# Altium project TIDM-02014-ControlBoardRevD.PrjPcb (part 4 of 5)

## Sheet Safety MCU.SchDoc
size 431 x 279 mm; Date: Not shown in title block; ApprovedBy: Not shown in title block; CheckedBy: Not shown in title block; Author: Not shown in title block; CompanyName: Not shown in title block; Engineer: Not shown in title block; Organization: Not shown in title block; Address1: Not shown in title block; Address2: Not shown in title block; Address3: Not shown in title block; Address4: Not shown in title block; DocumentNumber: 17; Revision: Use project parameter SCH_Rev; SheetNumber: 18; SheetTotal: 19; PageSetup: Record=PageOptions¦CenterHorizontal=True¦CenterVertical=True¦PrintScale=1.00¦XCorrection=1.00¦YCorrection=1.00¦PrintKind=0¦BorderSize=5000000¦LeftOffset=0¦BottomOffset=0¦Orientation=2¦PaperLength=1000¦PaperWidth=1000¦Scale=100¦PaperSource=15¦PrintQuality=600¦MediaType=1¦DitherType=10¦PaperKind=Letter¦PrintScaleMode=1
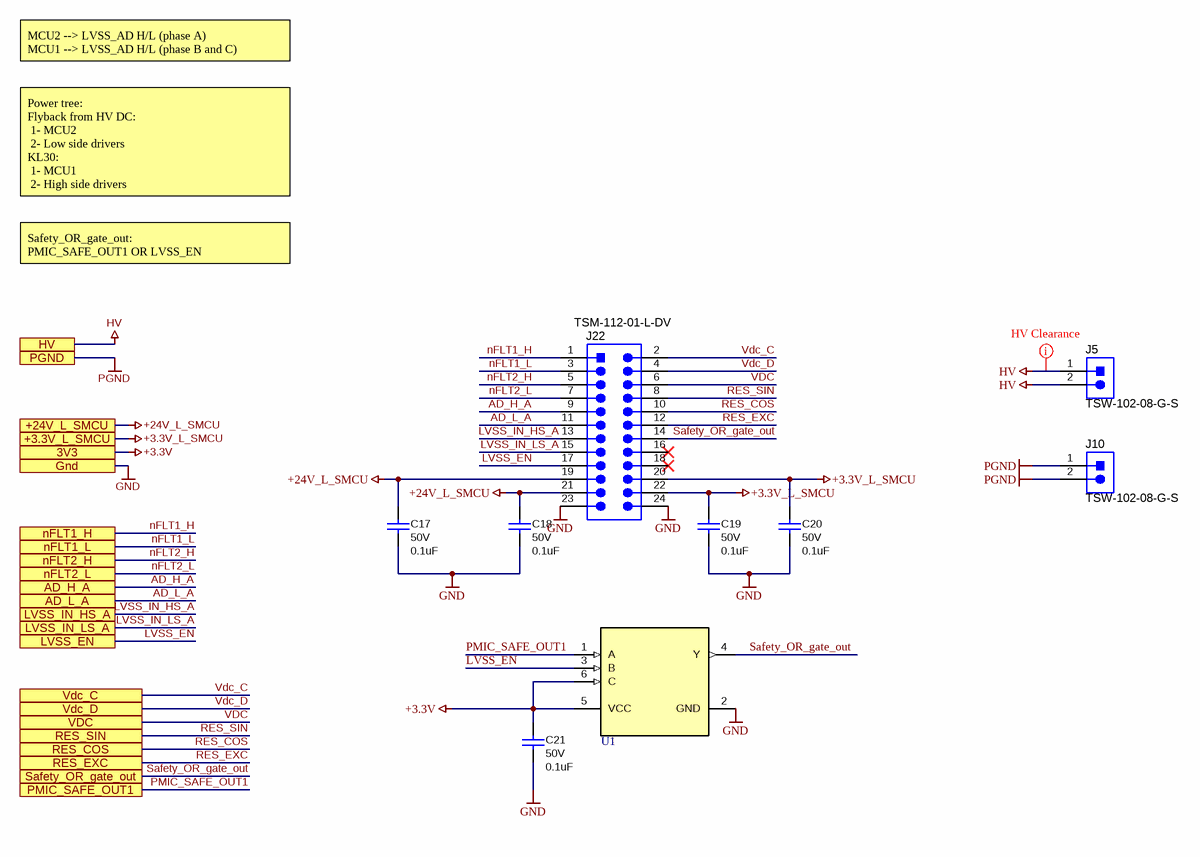
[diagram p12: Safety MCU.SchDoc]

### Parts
C17  VDC_V: 50V  ValueDisplayed: 0.1uF  [0603]  (hidden comment: CGA3E2X7R1H104K080AA)
C18  VDC_V: 50V  ValueDisplayed: 0.1uF  [0603]  (hidden comment: CGA3E2X7R1H104K080AA)
C19  VDC_V: 50V  ValueDisplayed: 0.1uF  [0603]  (hidden comment: CGA3E2X7R1H104K080AA)
C20  VDC_V: 50V  ValueDisplayed: 0.1uF  [0603]  (hidden comment: CGA3E2X7R1H104K080AA)
C21  VDC_V: 50V  ValueDisplayed: 0.1uF  [0603]  (hidden comment: CGA3E2X7R1H104K080AA)
J5  TSW-102-08-G-S  [Samtec_TSW-102-08-x-S]
J10  TSW-102-08-G-S  [Samtec_TSW-102-08-x-S]
J22  TSM-112-01-L-DV  [Samtec_TSM-112-01-x-DV]
U1  SN74LVC1G3208DBVR  [DBV0006A_N]  (value not drawn)

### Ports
3V3, +3.3V_L_SMCU, +24V_L_SMCU, AD_H_A, AD_L_A, Gnd, HV, LVSS_EN, LVSS_IN_HS_A, LVSS_IN_LS_A, nFLT1_H, nFLT1_L, nFLT2_H, nFLT2_L, PGND, PMIC_SAFE_OUT1, RES_COS, RES_EXC, RES_SIN, Safety_OR_gate_out, VDC, Vdc_C, Vdc_D

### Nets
+3.3V: C21.1 U1.5(VCC) U1.6(C) ; port 3V3
+3.3V_L_SMCU: C19.1 C20.1 J22.20 J22.22 ; port +3.3V_L_SMCU  [project net 3V3_L_SMCU_IN]
+24V_L_SMCU: C17.1 C18.1 J22.19 J22.21 ; port +24V_L_SMCU  [project net 24V_L_SMCU_IN]
GND: C17.2 C18.2 C19.2 C20.2 C21.2 J22.23 J22.24 U1.2(GND) ; port Gnd
HV: J5.1 J5.2 ; port HV
PGND: J10.1 J10.2 ; port PGND  [project net Pgndin]
AD_H_A: J22.9 ; port AD_H_A
AD_L_A: J22.11 ; port AD_L_A
LVSS_EN: J22.17 U1.3(B) ; port LVSS_EN
LVSS_IN_HS_A: J22.13 ; port LVSS_IN_HS_A
LVSS_IN_LS_A: J22.15 ; port LVSS_IN_LS_A
nFLT1_H: J22.1 ; port nFLT1_H
nFLT1_L: J22.3 ; port nFLT1_L
nFLT2_H: J22.5 ; port nFLT2_H
nFLT2_L: J22.7 ; port nFLT2_L
PMIC_SAFE_OUT1: U1.1(A) ; port PMIC_SAFE_OUT1
RES_COS: J22.10 ; port RES_COS
RES_EXC: J22.12 ; port RES_EXC
RES_SIN: J22.8 ; port RES_SIN
Safety_OR_gate_out: J22.14 U1.4(Y) ; port Safety_OR_gate_out
VDC: J22.6 ; port VDC
Vdc_C: J22.2 ; port Vdc_C
Vdc_D: J22.4 ; port Vdc_D

Not connected (* = marked no-connect by the designer): J22 16* 18*

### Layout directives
net class HVC: HV

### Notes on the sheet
- MCU2 --> LVSS_AD H/L (phase A)
  MCU1 --> LVSS_AD H/L (phase B and C)
- Power tree:
  Flyback from HV DC:
  1- MCU2
  2- Low side drivers
  KL30:
  1- MCU1
  2- High side drivers
- Safety_OR_gate_out:
  PMIC_SAFE_OUT1 OR LVSS_EN

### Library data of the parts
C17-C21 = CMP-0007078-4: CAP, CERM, 0.1 uF, 50 V, +/- 10%, X7R, AEC-Q200 Grade 1, 0603; Manufacturer: TDK; TaMin_C: -55°C; ESR_ohm: 29.6m; Polarized: N; SizeAreaWB_mm2: 4.68; Value1: 0.0296 ohm; U/M: EA; Value: 0.1uF; TaMax_C: 125°C; SizeZ_mm: 1; SizeX_mm: 1.6; SizeY_mm: 0.8; SizeArea_mm2: 1.28; AEC Qualified: Y; Cap_F: 100nF; IRMS_A: 971.99mA; AEC Category: Q200
J5 J10 = CMP-0077643-1: Header, 2.54mm, 2x1, Gold, TH; Manufacturer: Samtec; Pitch_mm: 2.54; Gender: Male; Cert_CSA: Y; Current_A: 5.7A; Voltage_V: 550V; Row_Count: 1
J22 = CMP-0055470-1: Header, 2.54mm, 12x2, Gold, SMT; Manufacturer: Samtec; CNHeader: TRUE; Shrouded: N; Gender: Male; Cert_CSA: Y; Voltage_V: 475V; Row_Count: 2; Pitch_mm: 2.54; CT: FALSE
U1 = CMP-0051001-1: Single 3-Input Positive OR-AND Gate, DBV0006A, LARGE T&R; Manufacturer: Texas Instruments; 3-State Output: No; Rating: Catalog; Technology Family: LVC; Sub-Family: Configurable Logic; ICC @ Nom Voltage(Max)(mA): 0.01; Input Type: CMOS/TTL; VCC(Max)(V): 5.5; Voltage(Nom)(V): 1.8,2.5,3.3,5; VCC(Min)(V): 1.65; Output Drive (IOL/IOH)(Max)(mA): 32/-32; Bits(#): 1; F @ Nom Voltage(Max)(Mhz): 150; tpd @ Nom Voltage(Max)(ns): 17.5,7.5,5.9,4.5; Output Type: CMOS; Gate Type: Configurable; Logic: True

## Sheet Safe State Behavior Settings.SchDoc
size 431 x 279 mm; Date: Not shown in title block; ApprovedBy: Not shown in title block; CheckedBy: Not shown in title block; Author: Not shown in title block; CompanyName: Not shown in title block; Engineer: Not shown in title block; Organization: Not shown in title block; Address1: Not shown in title block; Address2: Not shown in title block; Address3: Not shown in title block; Address4: Not shown in title block; DocumentNumber: 16; Revision: Use project parameter SCH_Rev; SheetNumber: 17; SheetTotal: 19; PageSetup: Record=PageOptions¦CenterHorizontal=True¦CenterVertical=True¦PrintScale=1.00¦XCorrection=1.00¦YCorrection=1.00¦PrintKind=0¦BorderSize=5000000¦LeftOffset=0¦BottomOffset=0¦Orientation=2¦PaperLength=1000¦PaperWidth=1000¦Scale=100¦PaperSource=15¦PrintQuality=600¦MediaType=1¦DitherType=10¦PaperKind=Letter¦PrintScaleMode=1
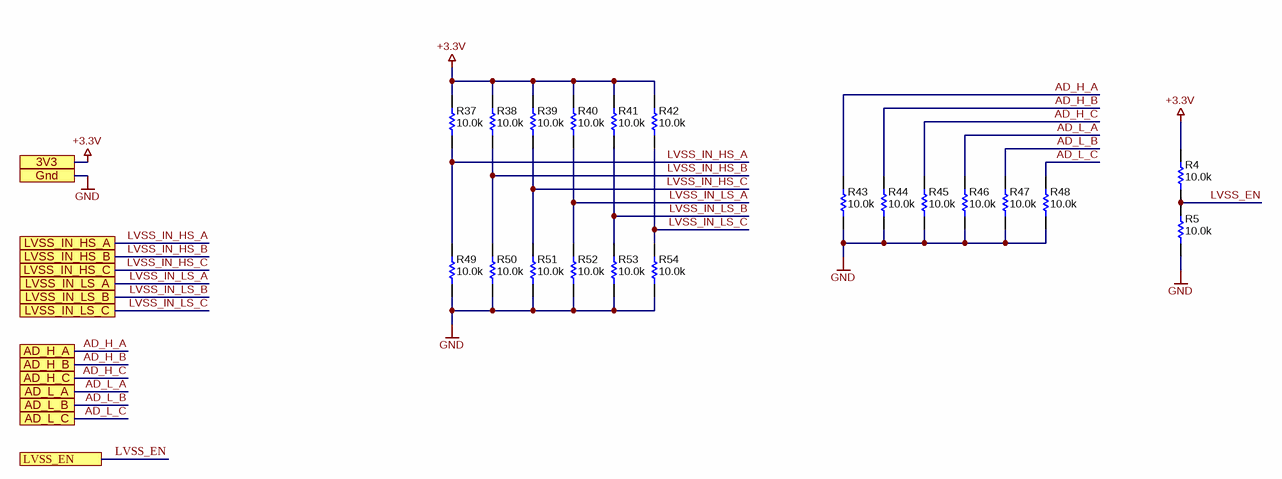
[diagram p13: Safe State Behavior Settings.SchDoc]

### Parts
R4  ValueDisplayed: 10.0k  [0603]  (hidden comment: CRCW060310K0FKEA)
R5  ValueDisplayed: 10.0k  [0603]  (hidden comment: CRCW060310K0FKEA)
R37  ValueDisplayed: 10.0k  [0603]  (hidden comment: CRCW060310K0FKEA)
R38  ValueDisplayed: 10.0k  [0603]  (hidden comment: CRCW060310K0FKEA)
R39  ValueDisplayed: 10.0k  [0603]  (hidden comment: CRCW060310K0FKEA)
R40  ValueDisplayed: 10.0k  [0603]  (hidden comment: CRCW060310K0FKEA)
R41  ValueDisplayed: 10.0k  [0603]  (hidden comment: CRCW060310K0FKEA)
R42  ValueDisplayed: 10.0k  [0603]  (hidden comment: CRCW060310K0FKEA)
R43  ValueDisplayed: 10.0k  [0603]  (hidden comment: CRCW060310K0FKEA)
R44  ValueDisplayed: 10.0k  [0603]  (hidden comment: CRCW060310K0FKEA)
R45  ValueDisplayed: 10.0k  [0603]  (hidden comment: CRCW060310K0FKEA)
R46  ValueDisplayed: 10.0k  [0603]  (hidden comment: CRCW060310K0FKEA)
R47  ValueDisplayed: 10.0k  [0603]  (hidden comment: CRCW060310K0FKEA)
R48  ValueDisplayed: 10.0k  [0603]  (hidden comment: CRCW060310K0FKEA)
R49  ValueDisplayed: 10.0k  [0603]  (hidden comment: CRCW060310K0FKEA)
R50  ValueDisplayed: 10.0k  [0603]  (hidden comment: CRCW060310K0FKEA)
R51  ValueDisplayed: 10.0k  [0603]  (hidden comment: CRCW060310K0FKEA)
R52  ValueDisplayed: 10.0k  [0603]  (hidden comment: CRCW060310K0FKEA)
R53  ValueDisplayed: 10.0k  [0603]  (hidden comment: CRCW060310K0FKEA)
R54  ValueDisplayed: 10.0k  [0603]  (hidden comment: CRCW060310K0FKEA)

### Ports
3V3, AD_H_A, AD_H_B, AD_H_C, AD_L_A, AD_L_B, AD_L_C, Gnd, LVSS_EN, LVSS_IN_HS_A, LVSS_IN_HS_B, LVSS_IN_HS_C, LVSS_IN_LS_A, LVSS_IN_LS_B, LVSS_IN_LS_C

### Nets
+3.3V: R4.2 R37.2 R38.2 R39.2 R40.2 R41.2 R42.2 ; port 3V3
GND: R5.1 R43.1 R44.1 R45.1 R46.1 R47.1 R48.1 R49.1 R50.1 R51.1 R52.1 R53.1 R54.1 ; port Gnd
AD_H_A: R43.2 ; port AD_H_A
AD_H_B: R44.2 ; port AD_H_B
AD_H_C: R45.2 ; port AD_H_C
AD_L_A: R46.2 ; port AD_L_A
AD_L_B: R47.2 ; port AD_L_B
AD_L_C: R48.2 ; port AD_L_C
LVSS_EN: R4.1 R5.2 ; port LVSS_EN
LVSS_IN_HS_A: R37.1 R49.2 ; port LVSS_IN_HS_A
LVSS_IN_HS_B: R38.1 R50.2 ; port LVSS_IN_HS_B
LVSS_IN_HS_C: R39.1 R51.2 ; port LVSS_IN_HS_C
LVSS_IN_LS_A: R40.1 R52.2 ; port LVSS_IN_LS_A
LVSS_IN_LS_B: R41.1 R53.2 ; port LVSS_IN_LS_B
LVSS_IN_LS_C: R42.1 R54.2 ; port LVSS_IN_LS_C

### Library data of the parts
R4 R5 R37-R54 = CMP-0021998-4: RES, 10.0 k, 1%, 0.1 W, AEC-Q200 Grade 0, 0603; Manufacturer: Vishay-Dale; Power_W: 100mW; TempCo: 100 ppm/C; Value_Code: 10k0; Value: 10.0k; EIA_Code: E96; Res_ohm: 10k; SizeX_mm: 1.6; SizeY_mm: 0.8; SizeZ_mm: 1; Value2: 0.1W; SizeArea_mm2: 1.28; AEC Qualified: Y; VDC_V: 75V; AEC Category: Q200; AEC Grade: 0

## Sheet voltage-sensing.SchDoc: HV Sensing
size 431 x 279 mm; Date: Not shown in title block; ApprovedBy: Not shown in title block; CheckedBy: Not shown in title block; Author: Not shown in title block; CompanyName: Not shown in title block; DrawnBy: Panacek; Engineer: Not shown in title block; Organization: Not shown in title block; Address1: Not shown in title block; Address2: Not shown in title block; Address3: Not shown in title block; Address4: Not shown in title block; DocumentNumber: 8; Revision: Use project parameter SCH_Rev; SheetNumber: 9; SheetTotal: 19; PageSetup: Record=PageOptions¦CenterHorizontal=True¦CenterVertical=True¦PrintScale=1.00¦XCorrection=1.00¦YCorrection=1.00¦PrintKind=0¦BorderSize=5000000¦LeftOffset=0¦BottomOffset=0¦Orientation=2¦PaperLength=1000¦PaperWidth=1000¦Scale=100¦PaperSource=15¦PrintQuality=600¦MediaType=1¦DitherType=10¦PaperKind=Letter¦PrintScaleMode=1
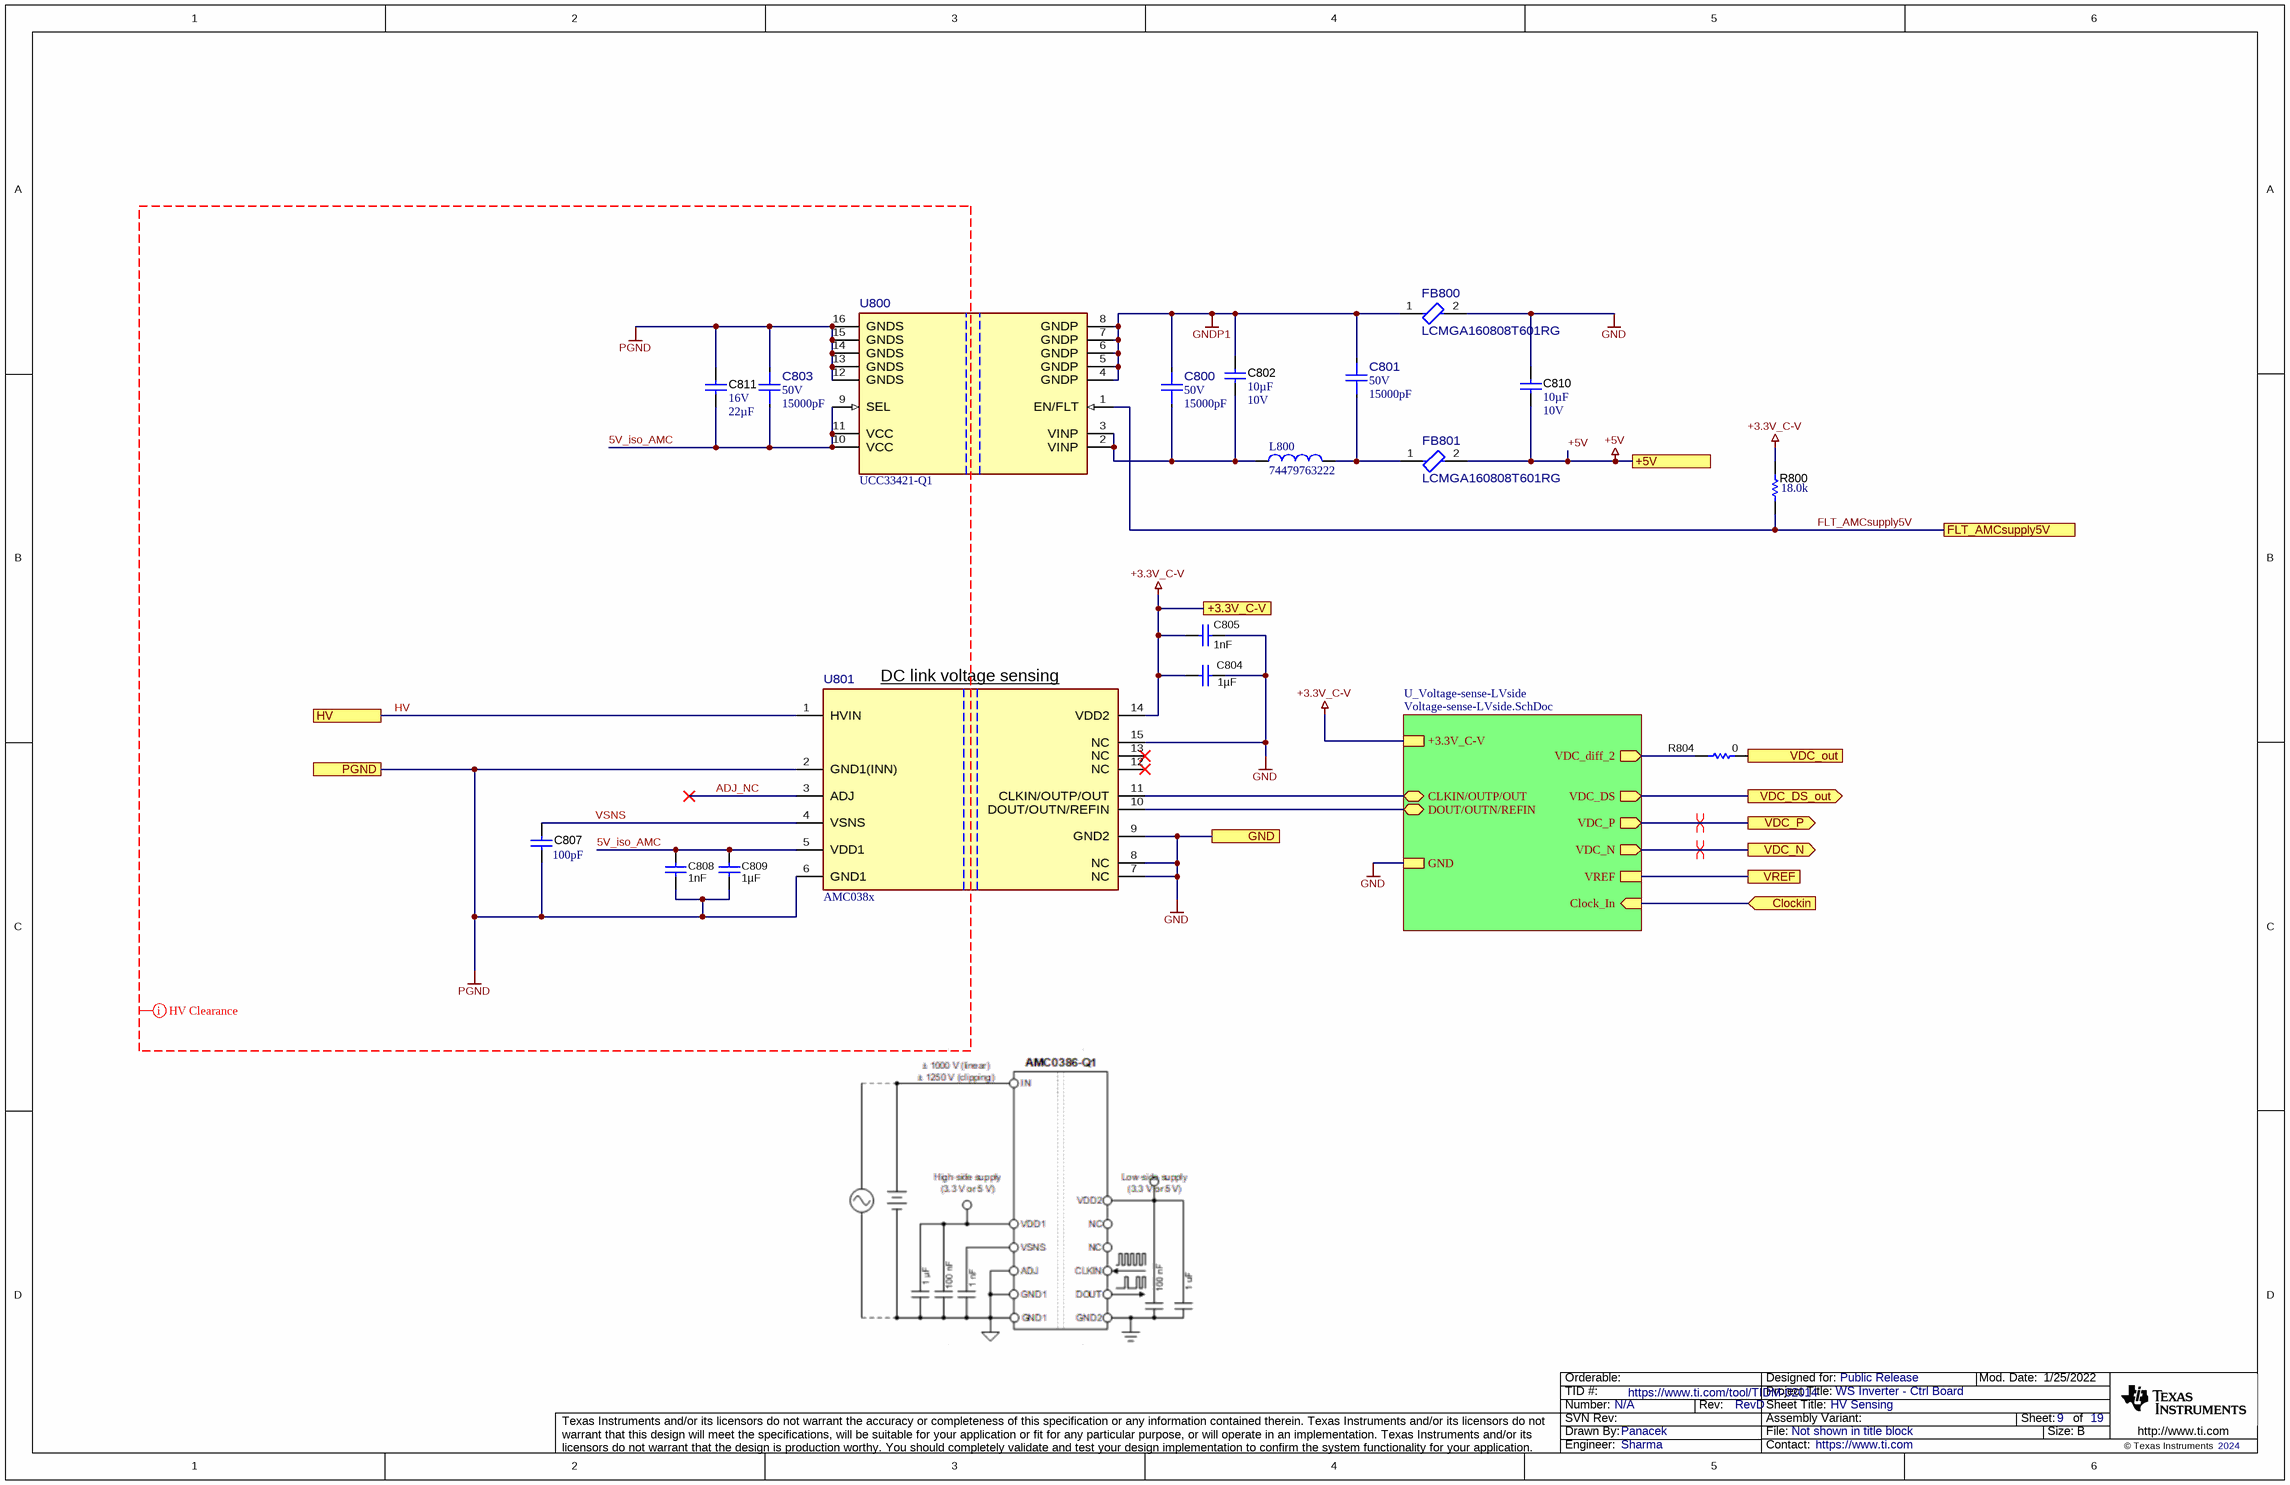
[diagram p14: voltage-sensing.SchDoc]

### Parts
C800  VDC_V: 50V  ValueDisplayed: 15000pF  [FP-GCM155R71H153KA55D_0402-MFG]  (hidden comment: GCM155R71H153KA55D)
C801  VDC_V: 50V  ValueDisplayed: 15000pF  [FP-GCM155R71H153KA55D_0402-MFG]  (hidden comment: GCM155R71H153KA55D)
C802  Cap_F: 10µF  VDC_V: 10V  [0805_HV]  (hidden comment: GCJ21BR71A106KE01L)
C803  VDC_V: 50V  ValueDisplayed: 15000pF  [FP-GCM155R71H153KA55D_0402-MFG]  (hidden comment: GCM155R71H153KA55D)
C804  Cap_F: 1µF  [0603]  (hidden comment: CGA3E1X7R1V105K080AC)
C805  Cap_F: 1nF  [0603]  (hidden comment: GRM1885C1H102JA01D)
C807  ValueDisplayed: 100pF  [0603]  (hidden comment: GRM1885C1H101JA01D)
C808  Cap_F: 1nF  [0603]  (hidden comment: GRM1885C1H102JA01D)
C809  Cap_F: 1µF  [0603]  (hidden comment: CGA3E1X7R1V105K080AC)
C810  Cap_F: 10µF  VDC_V: 10V  [0805_HV]  (hidden comment: GCJ21BR71A106KE01L)
C811  VDC_V: 16V  ValueDisplayed: 22µF  [0603]  (hidden comment: CL10A226MO7JZNC)
FB800  LCMGA160808T601RG  [FP-LCMGA160808T601RG_0603-MFG]
FB801  LCMGA160808T601RG  [FP-LCMGA160808T601RG_0603-MFG]
L800  74479763222  [WE-PMI_0603_L1.6W0.8H0.8]
R800  ValueDisplayed: 18.0k  [0603]  (hidden comment: RC0603FR-0718KL)
R804  ValueDisplayed: 0  [0603]  (hidden comment: CRCW06030000Z0EA)
U800  UCC33421-Q1  [DWX0016A-MFG]
U801  AMC038x  [DFX0015-MFG]

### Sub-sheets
U_Voltage-sense-LVside = Voltage-sense-LVside.SchDoc: CLKIN/OUTP/OUT (bidir), DOUT/OUTN/REFIN (bidir), Clock_In (in), VDC_diff_2 (out), VDC_DS (out), +3.3V_C-V, GND, VDC_P (out), VDC_N (out), VREF

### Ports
+3.3V_C-V, +5V, Clockin (in), FLT_AMCsupply5V, GND, HV, PGND, VDC_DS_out (out), VDC_N (out), VDC_out (out), VDC_P (out), VREF

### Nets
+3.3V_C-V: C804.1 C805.1 R800.2 U801.14(VDD2) ; port +3.3V_C-V, sheet U_Voltage-sense-LVside/+3.3V_C-V
+5V: C810.2 FB801.2 ; port +5V
GND: C804.2 C805.2 C810.1 FB800.2 U801.7(NC) U801.8(NC) U801.9(GND2) U801.15(NC) ; port GND, sheet U_Voltage-sense-LVside/GND
GNDP1: C800.2 C801.2 C802.1 FB800.1 U800.4(GNDP) U800.5(GNDP) U800.6(GNDP) U800.7(GNDP) U800.8(GNDP)
HV: U801.1(HVIN) ; port HV
PGND: C803.2 C807.2 C808.1 C809.1 C811.1 U800.12(GNDS) U800.13(GNDS) U800.14(GNDS) U800.15(GNDS) U800.16(GNDS) U801.2(GND1(INN)) U801.6(GND1) ; port PGND  [project net Pgndin]
VREF: port VREF, sheet U_Voltage-sense-LVside/VREF
5V_iso_AMC: C803.1 C808.2 C809.2 C811.2 U800.9(SEL) U800.10(VCC) U800.11(VCC) U801.5(VDD1)  [project net 5V_iso_AMC_9]
ADJ_NC: U801.3(ADJ)  [project net ADJ_NC_9]
CLKIN/OUTP/OUT: U801.11(CLKIN/OUTP/OUT) ; sheet U_Voltage-sense-LVside/CLKIN/OUTP/OUT
DOUT/OUTN/REFIN: U801.10(DOUT/OUTN/REFIN) ; sheet U_Voltage-sense-LVside/DOUT/OUTN/REFIN
FLT_AMCsupply5V: R800.1 U800.1(EN/FLT) ; port FLT_AMCsupply5V
VDC: R804.2 ; port VDC_out
Vdc_C: port Clockin, sheet U_Voltage-sense-LVside/Clock_In
Vdc_D: port VDC_DS_out, sheet U_Voltage-sense-LVside/VDC_DS
VDC_diff_2: R804.1 ; sheet U_Voltage-sense-LVside/VDC_diff_2
VDC_N: port VDC_N, sheet U_Voltage-sense-LVside/VDC_N
VDC_P: port VDC_P, sheet U_Voltage-sense-LVside/VDC_P
VSNS: C807.1 U801.4(VSNS)  [project net VSNS_9]
NetC800_1: C800.1 C802.2 L800.1 U800.2(VINP) U800.3(VINP)
NetC801_1: C801.1 FB801.1 L800.2

Not connected (* = marked no-connect by the designer): U801 12(NC)* 13(NC)*

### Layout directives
net class HVC: 5V_iso_AMC, ADJ_NC, HV, PGND, VSNS
differential pair: VDC_N, VDC_P

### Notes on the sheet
- (near U801) DC link voltage sensing

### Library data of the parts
C800 C801 C803 = CMP-0090630-1: 0.015µF ±10% 50V Ceramic Capacitor X7R 0402 (1005 Metric); Manufacturer: Murata; SizeZ_mm: 0.55mm; AEC Qualified: Yes; AEC Grade: Grade 1; Value: 15nF; TempCo: 15%
C802 C810 = CMP-0079153-1: CAP, CERM, 10 µF, 10 V,+/- 10%, X7R, AEC-Q200 Grade 1, 0805; Manufacturer: MuRata; SizeAreaWB_mm2: 6.75; SizeArea_mm2: 2.5; AEC Qualified: Y; AEC Category: Q200; Value: 10uF; TaMax_C: 125°C; SizeZ_mm: 1.45; AEC Grade: 1; Polarized: N; TaMin_C: -55°C; SizeY_mm: 1.25; U/M: EA; SizeX_mm: 2; Cap_Case: 0805
C804 C809 = CMP-0007067-4: CAP, CERM, 1 uF, 35 V, +/- 10%, X7R, AEC-Q200 Grade 1, 0603; Manufacturer: TDK; TaMin_C: -55°C; Polarized: N; SizeAreaWB_mm2: 4.68; Value1: 0.005522 ohm; U/M: EA; Value: 1uF; TaMax_C: 125°C; SizeZ_mm: 1; SizeX_mm: 1.6; SizeY_mm: 0.8; Value2: 35V; SizeArea_mm2: 1.28; AEC Qualified: Y; AEC Category: Q200; ESR_ohm: 5.522m; IRMS_A: 2.2162A
C805 C808 = CMP-0007173-4: CAP, CERM, 1000 pF, 50 V, +/- 5%, C0G/NP0, 0603; Manufacturer: MuRata; TaMin_C: -55°C; Polarized: N; SizeAreaWB_mm2: 4.68; Value1: Unknown; U/M: EA; Value: 1000pF; TaMax_C: 125°C; SizeZ_mm: 1; SizeX_mm: 1.6; SizeY_mm: 0.8; Value2: 50V; SizeArea_mm2: 1.28; AEC Category: Q200
C807 = CMP-0007171-4: CAP, CERM, 100 pF, 50 V, +/- 5%, C0G/NP0, 0603; Manufacturer: MuRata; TaMin_C: -55°C; Polarized: N; SizeAreaWB_mm2: 4.68; Value1: Unknown; U/M: EA; Value: 100pF; TaMax_C: 125°C; SizeZ_mm: 1; SizeX_mm: 1.6; SizeY_mm: 0.8; Value2: 50V; SizeArea_mm2: 1.28; AEC Category: Q200
C811 = CMP-0081159-1: CAP, CERM, 22 µF, 16 V,+/- 20%, X5R, 0603; Manufacturer: Samsung; SizeAreaWB_mm2: 4.68; SizeArea_mm2: 1.28; AEC Qualified: N; AEC Category: Q200; Value: 22uF; TaMax_C: 85°C; SizeZ_mm: 1; TaMin_C: -55°C; SizeY_mm: 0.8; U/M: EA; SizeX_mm: 1.6
FB800 FB801 = CMP-0124053-1: Ferrite Bead 600Ohm 0.9A 0.17Ohm Wirewound 2-Pin 0603 Paper T/R; Manufacturer: Taiyo Yuden; DCR_ohm: 0.17; Imax_A: 900mA; SizeZ_mm: 0.9mm; AEC Grade: Grade 1; AEC Qualified: Yes; Impedance At Frequency: 600Ω @ 100MHz; Tolerance_%: 25%
L800 = CMP-1392-00025-2: NexarPartId: 38797936; Manufacturer: Wurth Elektronik; DC Resistance (DCR): 300mΩ; Inductance: 2.2µH; Current Rating: 550mA
R800 = CMP-0022852-5: RES, 18.0 k, 1%, 0.1 W, 0603; Manufacturer: Yageo; Power_W: 100mW; TempCo: 100 ppm/C; Value_Code: 18k0; Value: 18.0k; Res_ohm: 18k; SizeX_mm: 1.6; SizeY_mm: 0.8; SizeZ_mm: 1; Value2: 0.1W; SizeArea_mm2: 1.28; AEC Qualified: N; VDC_V: 75V; AEC Category: Q200; SizeAreaWB_mm2: 4.68
R804 = CMP-0025697-4: RES, 0, 5%, 0.1 W, AEC-Q200 Grade 0, 0603; Manufacturer: Vishay-Dale; Power_W: 100mW; TempCo: 200 ppm/C; Value_Code: 0000; Value: 0; EIA_Code: E24; SizeX_mm: 1.6; SizeY_mm: 0.8; SizeZ_mm: 1; Value2: 0.1W; SizeArea_mm2: 1.28; AEC Qualified: Y; VDC_V: 75V; AEC Category: Q200
U800 = CMP-0120108-2: 1.5W, High-Density, >5 kVRMS Isolated DC-DC Converter; Manufacturer: Texas Instruments; SizeZ_mm: 2.6mm; AEC Qualified: No; Max Supply Voltage: 5.5V; Min Supply Voltage: 4.5V; Number Of Outputs: 1; Output Type: AdjustableProgrammable; Output Voltage: 5/5.5V; Standoff Height: 0.14mm; AEC Category: Q200; CompType: IC
U801 = CMP-0034316-3: Isolated Amplifiers for direct HV Sensing; Manufacturer: Texas Instruments; SizeZ_mm: 3.55mm; Standoff Height: 0.1mm; AEC Category: Q200; CompType: IC

## Sheet Voltage-sense-LVside.SchDoc
size 431 x 279 mm; Date: Not shown in title block; ApprovedBy: Not shown in title block; CheckedBy: Not shown in title block; Author: Not shown in title block; CompanyName: Not shown in title block; Engineer: Not shown in title block; Organization: Not shown in title block; Address1: Not shown in title block; Address2: Not shown in title block; Address3: Not shown in title block; Address4: Not shown in title block; DocumentNumber: 13; Revision: Use project parameter SCH_Rev; SheetNumber: 10; SheetTotal: 19; PageSetup: Record=PageOptions¦CenterHorizontal=True¦CenterVertical=True¦PrintScale=1.00¦XCorrection=1.00¦YCorrection=1.00¦PrintKind=0¦BorderSize=5000000¦LeftOffset=0¦BottomOffset=0¦Orientation=2¦PaperLength=1000¦PaperWidth=1000¦Scale=100¦PaperSource=15¦PrintQuality=600¦MediaType=1¦DitherType=10¦PaperKind=Letter¦PrintScaleMode=1
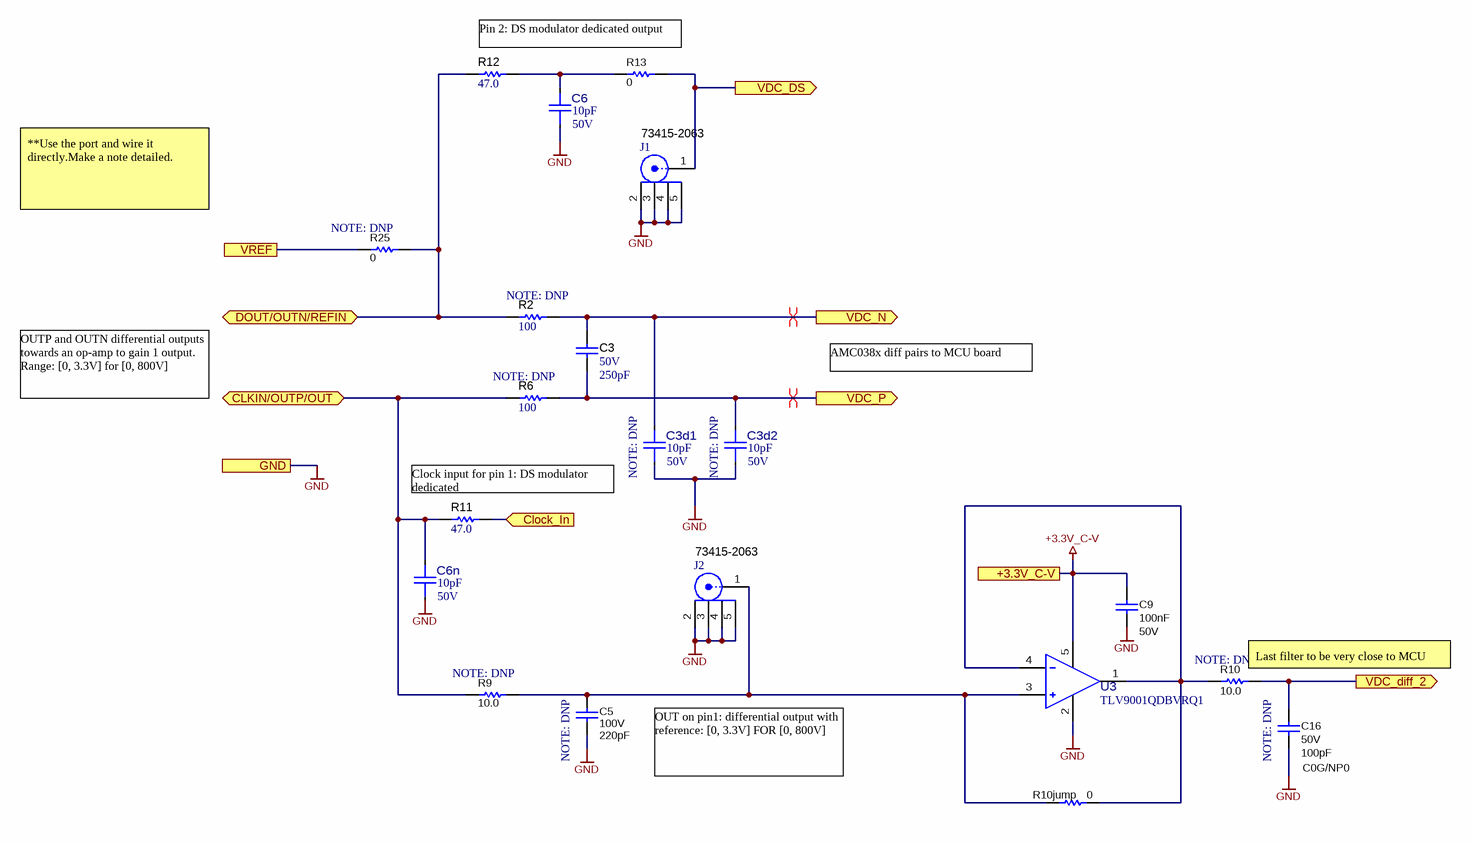
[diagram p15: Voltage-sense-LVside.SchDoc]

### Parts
C3  VDC_V: 50V  ValueDisplayed: 250pF  [0603]  (hidden comment: 06035A251JAT2A)
C3d1  Cap_F: 10pF  VDC_V: 50V  [FP-06035C100KAT2A_0603-MFG]  (hidden comment: 06035C100KAT2A)
C3d2  Cap_F: 10pF  VDC_V: 50V  [FP-06035C100KAT2A_0603-MFG]  (hidden comment: 06035C100KAT2A)
C5  VDC_V: 100V  ValueDisplayed: 220pF  [0603]  (hidden comment: GCM1885C2A221JA16D)
C6  Cap_F: 10pF  VDC_V: 50V  [FP-06035C100KAT2A_0603-MFG]  (hidden comment: 06035C100KAT2A)
C6n  Cap_F: 10pF  VDC_V: 50V  [FP-06035C100KAT2A_0603-MFG]  (hidden comment: 06035C100KAT2A)
C9  Cap_F: 100nF  VDC_V: 50V  [0603]  (hidden comment: CGA3E2X7R1H104K080AA)
C16  TempCo: C0G/NP0  VDC_V: 50V  ValueDisplayed: 100pF  [0603]  (hidden comment: CGA3E2NP01H101J080AA)
J1  73415-2063  [Molex_73415-2063]
J2  73415-2063  [Molex_73415-2063]
R2  ValueDisplayed: 100  [0603]  (hidden comment: RC0603FR-07100RL)
R6  ValueDisplayed: 100  [0603]  (hidden comment: RC0603FR-07100RL)
R9  ValueDisplayed: 10.0  [0603]  (hidden comment: CRCW060310R0FKEA)
R10  ValueDisplayed: 10.0  [0603]  (hidden comment: CRCW060310R0FKEA)
R10jump  ValueDisplayed: 0  [5106]  (hidden comment: 5106)
R11  ValueDisplayed: 47.0  [0603]  (hidden comment: CRCW060347R0FKEA)
R12  ValueDisplayed: 47.0  [0603]  (hidden comment: CRCW060347R0FKEA)
R13  ValueDisplayed: 0  [0603]  (hidden comment: CRCW06030000Z0EA)
R25  ValueDisplayed: 0  [0603]  (hidden comment: CRCW06030000Z0EA)
U3  TLV9001QDBVRQ1  [DBV0005A-MFG]

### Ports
+3.3V_C-V, CLKIN/OUTP/OUT (bidir), Clock_In (in), DOUT/OUTN/REFIN (bidir), GND, VDC_diff_2 (out), VDC_DS (out), VDC_N (out), VDC_P (out), VREF

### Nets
+3.3V_C-V: C9.1 U3.5(V+) ; port +3.3V_C-V
GND: C3d1.1 C3d2.1 C5.2 C6.1 C6n.1 C9.2 C16.2 J1.2 J1.3 J1.4 J1.5 J2.2 J2.3 J2.4 J2.5 U3.2(V-) ; port GND
VREF: R25.1 ; port VREF
CLKIN/OUTP/OUT: C6n.2 R6.1 R9.1 R11.1 ; port CLKIN/OUTP/OUT
DOUT/OUTN/REFIN: R2.1 R12.1 R25.2 ; port DOUT/OUTN/REFIN
Vdc_C: R11.2 ; port Clock_In
Vdc_D: J1.1 R13.2 ; port VDC_DS
VDC_diff_2: C16.1 R10.2 ; port VDC_diff_2
VDC_N: C3.1 C3d1.2 R2.2 ; port VDC_N
VDC_P: C3.2 C3d2.2 R6.2 ; port VDC_P
NetC5_1: C5.1 J2.1 R9.2 R10jump.2 U3.3(IN+)
NetC6_2: C6.2 R12.2 R13.1
NetR10_1: R10.1 R10jump.1 U3.1(OUT) U3.4(IN-)

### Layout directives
differential pair: VDC_N, VDC_P

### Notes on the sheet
- Pin 2: DS modulator dedicated output
- **Use the port and wire it directly.Make a note detailed.
- (near R25) NOTE: DNP
- (near R2) NOTE: DNP
- OUTP and OUTN differential outputs towards an op-amp to gain 1 output. Range: [0, 3.3V] for [0, 800V]
- (near R6) NOTE: DNP
- AMC038x diff pairs to MCU board
- Clock input for pin 1: DS modulator dedicated
- (near C3d1) NOTE: DNP
- (near C3d2) NOTE: DNP
- (near R9) NOTE: DNP
- (near R10) NOTE: DNP
- (near R10) Last filter to be very close to MCU connector
- (near C5) NOTE: DNP
- (near C16) NOTE: DNP
- OUT on pin1: differential output with reference: [0, 3.3V] FOR [0, 800V]

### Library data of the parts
C3 = CMP-0086095-1: CAP, CERM, 250 pF, 50 V,+/- 5%, C0G/NP0, 0603; Manufacturer: AVX; SizeX_mm: 1.6; AEC Category: Q200; TaMax_C: 125°C; TaMin_C: -55°C; SizeAreaWB_mm2: 4.68; Value: 0.00025uF; Polarized: N; SizeY_mm: 0.8; U/M: EA; SizeZ_mm: 1; SizeArea_mm2: 1.28
C3d1 C3d2 C6 C6n = CMP-0046668-1: 10 pF ±10% 50V Ceramic Capacitor X7R 0603 (1608 Metric); Manufacturer: KYOCERA AVX; AEC Qualified: No; SizeZ_mm: 0.9mm; TempCo: 15%; Value: 10pF
C5 = CMP-0860912-1: CAP, CERM, 220 pF, 100 V,+/- 5%, C0G/NP0, AEC-Q200 Grade 1, 0603; Manufacturer: MuRata; TaMin_C: -55°C; Polarized: N; SizeAreaWB_mm2: 4.68; U/M: EA; Value: 220pF; TaMax_C: 125°C; SizeZ_mm: 1; SizeX_mm: 1.6; SizeY_mm: 0.8; SizeArea_mm2: 1.28; AEC Qualified: Y; AEC Category: Q200
C9 = CMP-0007078-4: CAP, CERM, 0.1 uF, 50 V, +/- 10%, X7R, AEC-Q200 Grade 1, 0603; Manufacturer: TDK; TaMin_C: -55°C; Polarized: N; SizeAreaWB_mm2: 4.68; Value1: 0.0296 ohm; U/M: EA; Value: 0.1uF; TaMax_C: 125°C; SizeZ_mm: 1; SizeX_mm: 1.6; SizeY_mm: 0.8; SizeArea_mm2: 1.28; AEC Qualified: Y; AEC Category: Q200; ESR_ohm: 29.6m; IRMS_A: 971.99mA
C16 = CMP-0007075-4: CAP, CERM, 100 pF, 50 V, +/- 5%, C0G/NP0, AEC-Q200 Grade 0, 0603; Manufacturer: TDK; TaMin_C: -55°C; Polarized: N; SizeAreaWB_mm2: 4.68; Value1: Unknown; U/M: EA; Value: 100pF; TaMax_C: 150°C; SizeZ_mm: 1; SizeX_mm: 1.6; SizeY_mm: 0.8; SizeArea_mm2: 1.28; AEC Qualified: Y; AEC Category: Q200; AEC Grade: 0
J1 J2 = CMP-0055256-1: MMCX JACK, 50 Ohm, Gold, SMT; Manufacturer: Molex; CNHeader: FALSE; Gender: Female; Row_Count: 1; Pitch_mm: 2.64
R2 R6 = CMP-0022736-4: RES, 100, 1%, 0.1 W, 0603; Manufacturer: Yageo; Power_W: 100mW; TempCo: 100 ppm/C; Value_Code: 100R; Value: 100; EIA_Code: E96; SizeX_mm: 1.6; SizeY_mm: 0.8; SizeZ_mm: 1; Value2: 0.1W; SizeArea_mm2: 1.28; AEC Qualified: N; VDC_V: 75V; AEC Category: Q200; SizeAreaWB_mm2: 4.68
R9 R10 = CMP-0022003-4: RES, 10.0, 1%, 0.1 W, AEC-Q200 Grade 0, 0603; Manufacturer: Vishay-Dale; Power_W: 100mW; TempCo: 100 ppm/C; Value_Code: 10R0; Value: 10.0; EIA_Code: E96; Res_ohm: 10; SizeX_mm: 1.6; SizeY_mm: 0.8; SizeZ_mm: 1; Value2: 0.1W; SizeArea_mm2: 1.28; AEC Qualified: Y; VDC_V: 75V; AEC Category: Q200; AEC Grade: 0
R10jump = CMP-0020833-2: RES, 0, 1%, 0.5 W, 0805; Manufacturer: Keystone; SizeArea_mm2: 2.5; AEC Qualified: N; AEC Category: Q200; Value: 0; SizeZ_mm: 0.84; SizeY_mm: 1.25; Power_W: 500mW; Value2: 0.5W; SizeX_mm: 2; TempCo: ppm/C; U/M: EA
R11 R12 = CMP-0081280-1: RES, 47.0, 1%, 0.1 W, AEC-Q200 Grade 0, 0603; Manufacturer: Vishay-Dale; Value_Code: 47R0; SizeAreaWB_mm2: 4.68; SizeArea_mm2: 1.28; AEC Qualified: Y; AEC Category: Q200; Res_ohm: 47; Value: 47.0; SizeZ_mm: 1; TempCo: 100 ppm/C; AEC Grade: 0; Power_W: 100mW; VDC_V: 75V; SizeY_mm: 0.8; Value2: 0.1W; SizeX_mm: 1.6
R13 R25 = CMP-0025697-4: as R804 on sheet voltage-sensing
U3 = CMP-0120546-1: Automotive, single-channel, 5.5-V 1-MHz rail-to-rail input and output operational amplifier 5-SOT-23 -40 to 125; Manufacturer: Texas Instruments; SizeZ_mm: 1.45mm; AEC Qualified: Yes; AEC Grade: Grade 1; Gain Bandwidth: 1MHz; Input Bias Current: 0.000005uA; Input Offset Voltage: 0.4mV; Max Dual Supply Voltage: 2.75V; Max Supply Voltage: 5.5V; Min Dual Supply Voltage: 900mV; Min Supply Voltage: 1.8V; Nominal Supply Current: 60uA; Number Of Channels: 1; Output Current Per Channel: 40mA; Response Time: 3us; Standoff Height: 0mm; TaMax_C: +125°C; TaMin_C: -40°C; TJmax_C: +150°C; Voltage Gain: 130dB

## Sheet current-sensing-lem.SchDoc: Current Sensing Front-End
size 431 x 279 mm; Date: Not shown in title block; ApprovedBy: Not shown in title block; CheckedBy: Not shown in title block; Author: Not shown in title block; CompanyName: Not shown in title block; DrawnBy: Panacek; Engineer: Not shown in title block; Organization: Not shown in title block; Address1: Not shown in title block; Address2: Not shown in title block; Address3: Not shown in title block; Address4: Not shown in title block; DocumentNumber: 7; Revision: Use project parameter SCH_Rev; SheetNumber: 7; SheetTotal: 18; PageSetup: Record=PageOptions¦CenterHorizontal=True¦CenterVertical=True¦PrintScale=1.00¦XCorrection=1.00¦YCorrection=1.00¦PrintKind=0¦BorderSize=5000000¦LeftOffset=0¦BottomOffset=0¦Orientation=2¦PaperLength=1000¦PaperWidth=1000¦Scale=100¦PaperSource=15¦PrintQuality=600¦MediaType=1¦DitherType=10¦PaperKind=Letter¦PrintScaleMode=1
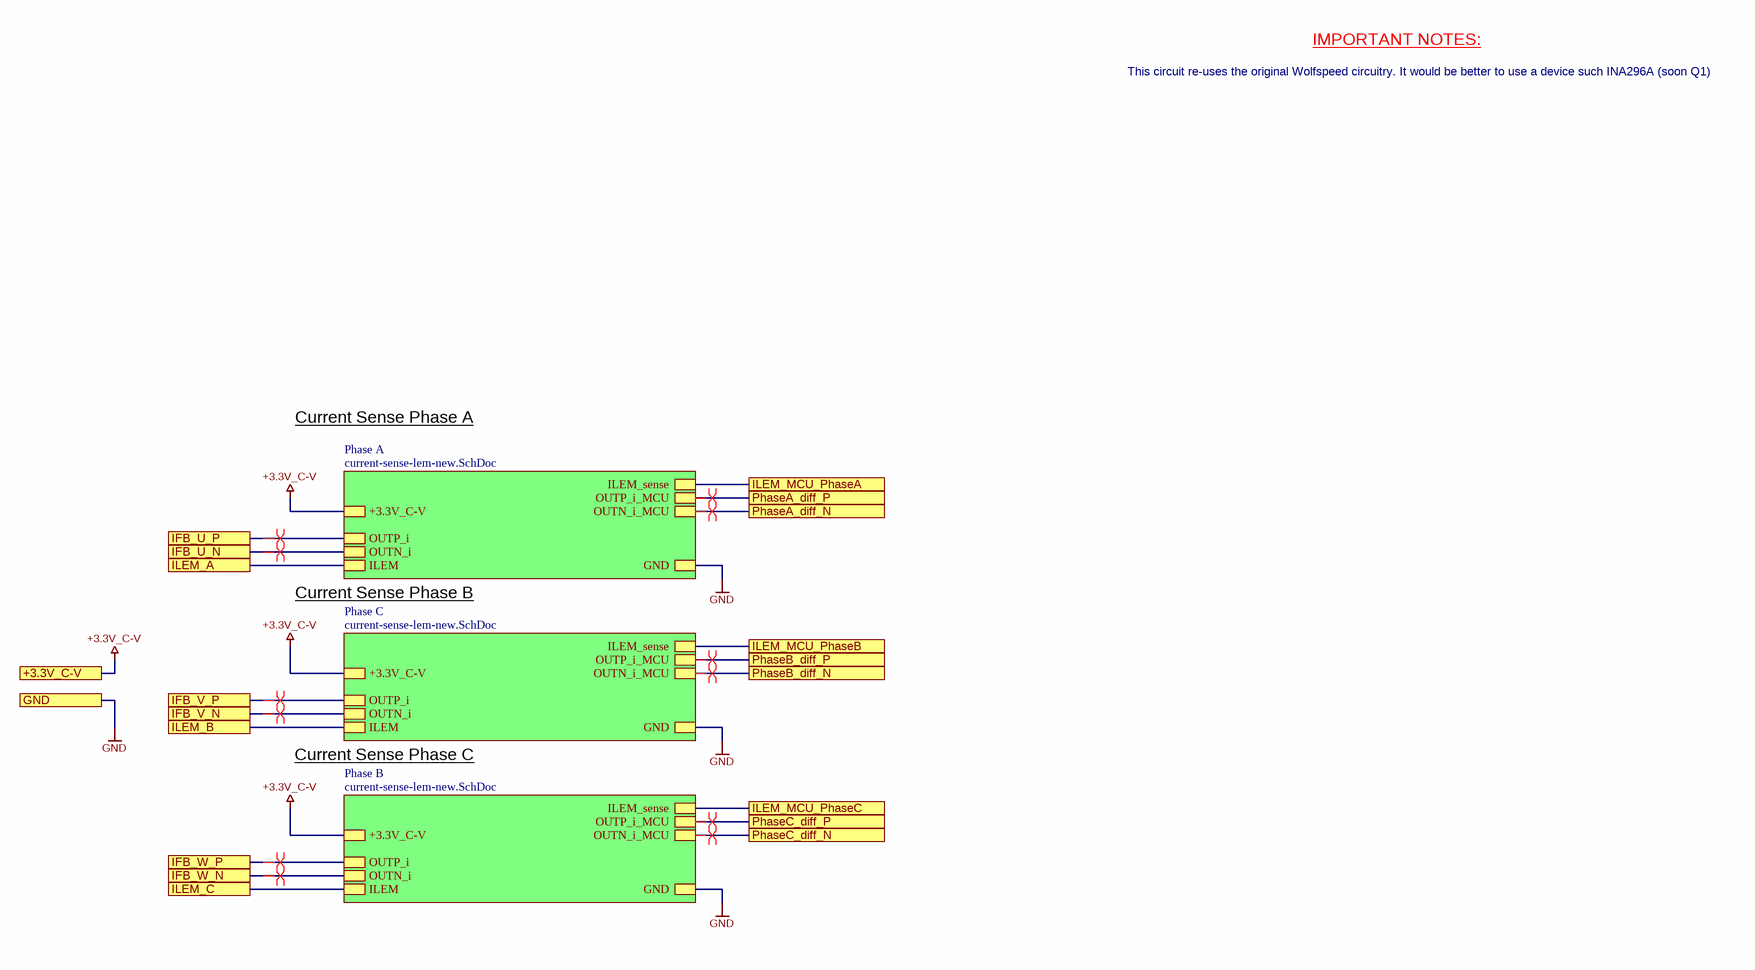
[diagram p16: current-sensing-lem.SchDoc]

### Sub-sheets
Phase A = current-sense-lem-new.SchDoc: GND, +3.3V_C-V, OUTP_i, OUTN_i, ILEM, ILEM_sense, OUTN_i_MCU, OUTP_i_MCU
Phase B = current-sense-lem-new.SchDoc: GND, +3.3V_C-V, OUTP_i, OUTN_i, ILEM, ILEM_sense, OUTN_i_MCU, OUTP_i_MCU
Phase C = current-sense-lem-new.SchDoc: GND, +3.3V_C-V, OUTP_i, OUTN_i, ILEM, ILEM_sense, OUTN_i_MCU, OUTP_i_MCU

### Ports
+3.3V_C-V, GND, IFB_U_N, IFB_U_P, IFB_V_N, IFB_V_P, IFB_W_N, IFB_W_P, ILEM_A, ILEM_B, ILEM_C, ILEM_MCU_PhaseA, ILEM_MCU_PhaseB, ILEM_MCU_PhaseC, PhaseA_diff_N, PhaseA_diff_P, PhaseB_diff_N, PhaseB_diff_P, PhaseC_diff_N, PhaseC_diff_P

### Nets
+3.3V_C-V: port +3.3V_C-V, sheet Phase A/+3.3V_C-V, sheet Phase C/+3.3V_C-V, sheet Phase B/+3.3V_C-V
GND: port GND, sheet Phase A/GND, sheet Phase C/GND, sheet Phase B/GND
IFB_U: port ILEM_MCU_PhaseA, sheet Phase A/ILEM_sense
IFB_U_N: port IFB_U_N, sheet Phase A/OUTN_i
IFB_U_P: port IFB_U_P, sheet Phase A/OUTP_i
IFB_V: port ILEM_MCU_PhaseB, sheet Phase C/ILEM_sense
IFB_V_N: port IFB_V_N, sheet Phase C/OUTN_i
IFB_V_P: port IFB_V_P, sheet Phase C/OUTP_i
IFB_W: port ILEM_MCU_PhaseC, sheet Phase B/ILEM_sense
IFB_W_N: port IFB_W_N, sheet Phase B/OUTN_i
IFB_W_P: port IFB_W_P, sheet Phase B/OUTP_i
ILEM_A: port ILEM_A, sheet Phase A/ILEM
ILEM_B: port ILEM_B, sheet Phase C/ILEM
ILEM_B: port ILEM_C, sheet Phase B/ILEM  [a separate net that carries the same name]
U_N: port PhaseA_diff_N, sheet Phase A/OUTN_i_MCU
U_P: port PhaseA_diff_P, sheet Phase A/OUTP_i_MCU
V_N: port PhaseB_diff_N, sheet Phase C/OUTN_i_MCU
V_P: port PhaseB_diff_P, sheet Phase C/OUTP_i_MCU
VOUT_C_N: port PhaseC_diff_N, sheet Phase B/OUTN_i_MCU
VOUT_C_P: port PhaseC_diff_P, sheet Phase B/OUTP_i_MCU

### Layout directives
differential pair: IFB_U_N, IFB_U_P, IFB_V_N, IFB_V_P, IFB_W_N, IFB_W_P, U_N, U_P, V_N, V_P, VOUT_C_N, VOUT_C_P

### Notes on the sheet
- IMPORTANT NOTES:
- This circuit re-uses the original Wolfspeed circuitry. It would be better to use a device such INA296A (soon Q1)
- Current Sense Phase A
- Current Sense Phase B
- Current Sense Phase C

## Sheet current-sense-lem-new.SchDoc
size 431 x 279 mm; Date: Not shown in title block; ApprovedBy: Not shown in title block; CheckedBy: Not shown in title block; Author: Not shown in title block; CompanyName: Not shown in title block; Engineer: Not shown in title block; Organization: Not shown in title block; Address1: Not shown in title block; Address2: Not shown in title block; Address3: Not shown in title block; Address4: Not shown in title block; DocumentNumber: 14; Revision: Use project parameter SCH_Rev; SheetNumber: 8; SheetTotal: 19; PageSetup: Record=PageOptions¦CenterHorizontal=True¦CenterVertical=True¦PrintScale=1.00¦XCorrection=1.00¦YCorrection=1.00¦PrintKind=0¦BorderSize=5000000¦LeftOffset=0¦BottomOffset=0¦Orientation=2¦PaperLength=1000¦PaperWidth=1000¦Scale=100¦PaperSource=15¦PrintQuality=600¦MediaType=1¦DitherType=10¦PaperKind=Letter¦PrintScaleMode=1
Used 3 times, as channels U_current-sensing-lem/Phase A, U_current-sensing-lem/Phase C, U_current-sensing-lem/Phase B. Parts and nets are listed once, with the designators drawn on the sheet.
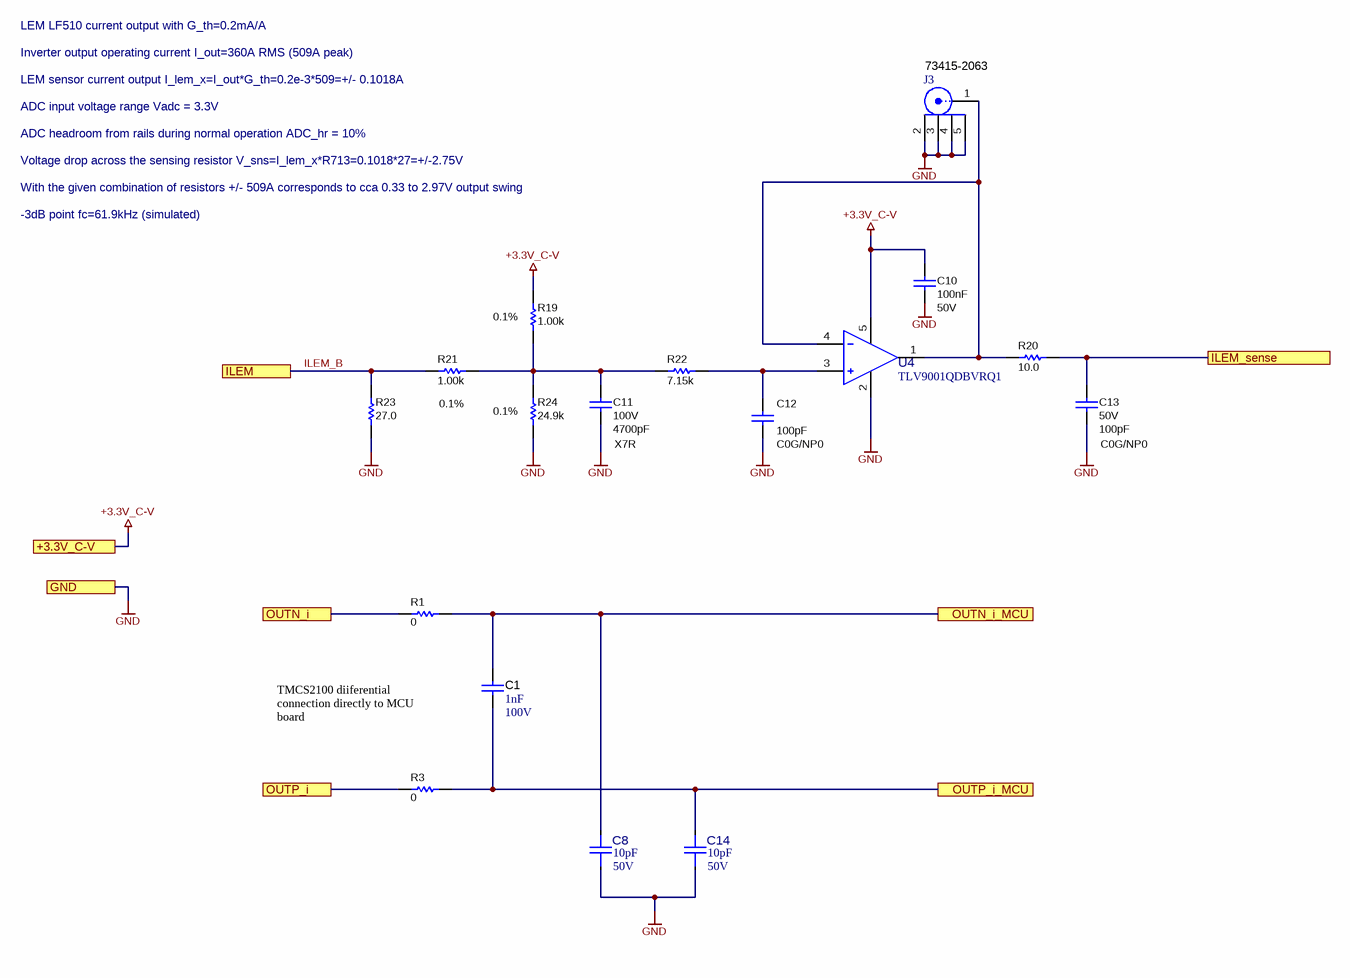
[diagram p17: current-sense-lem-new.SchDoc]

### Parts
C1  Cap_F: 1nF  VDC_V: 100V  [0603]  (hidden comment: 06031C102KAT2A)
C8  Cap_F: 10pF  VDC_V: 50V  [FP-06035C100KAT2A_0603-MFG]  (hidden comment: 06035C100KAT2A)
C10  Cap_F: 100nF  VDC_V: 50V  [0603]  (hidden comment: CGA3E2X7R1H104K080AA)
C11  TempCo: X7R  VDC_V: 100V  ValueDisplayed: 4700pF  [0603]  (hidden comment: GCM188R72A472KA37D)
C12  TempCo: C0G/NP0  ValueDisplayed: 100pF  [0603]  (hidden comment: CGA3E2NP01H101J080AA)
C13  TempCo: C0G/NP0  VDC_V: 50V  ValueDisplayed: 100pF  [0603]  (hidden comment: CGA3E2NP01H101J080AA)
C14  Cap_F: 10pF  VDC_V: 50V  [FP-06035C100KAT2A_0603-MFG]  (hidden comment: 06035C100KAT2A)
J3  73415-2063  [Molex_73415-2063]
R1  ValueDisplayed: 0  [0603]  (hidden comment: CRCW06030000Z0EA)
R3  ValueDisplayed: 0  [0603]  (hidden comment: CRCW06030000Z0EA)
R19  Value1: 0.1%  ValueDisplayed: 1.00k  [0603]  (hidden comment: ERA3AEB102V)
R20  ValueDisplayed: 10.0  [0603]  (hidden comment: CRCW060310R0FKEA)
R21  Value1: 0.1%  ValueDisplayed: 1.00k  [0603]  (hidden comment: ERA3AEB102V)
R22  ValueDisplayed: 7.15k  [0603]  (hidden comment: CRCW06037K15FKEA)
R23  ValueDisplayed: 27.0  [2512]  (hidden comment: CRCW251227R0FKEG)
R24  Tolerance_%: 0.1%  ValueDisplayed: 24.9k  [0603]  (hidden comment: ERA-3AEB2492V)
U4  TLV9001QDBVRQ1  [DBV0005A-MFG]

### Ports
+3.3V_C-V, GND, ILEM, ILEM_sense, OUTN_i, OUTN_i_MCU, OUTP_i, OUTP_i_MCU

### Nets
+3.3V_C-V: C10.1 R19.2 U4.5(V+) ; port +3.3V_C-V
GND: C8.1 C10.2 C11.2 C12.2 C13.2 C14.1 J3.2 J3.3 J3.4 J3.5 R23.1 R24.1 U4.2(V-) ; port GND
ILEM_B: R21.1 R23.2 ; port ILEM
ILEM_sense: C13.1 R20.2 ; port ILEM_sense
OUTN_i: R1.1 ; port OUTN_i
OUTN_i_MCU: C1.1 C8.2 R1.2 ; port OUTN_i_MCU
OUTP_i: R3.1 ; port OUTP_i
OUTP_i_MCU: C1.2 C14.2 R3.2 ; port OUTP_i_MCU
NetC11_1: C11.1 R19.1 R21.2 R22.1 R24.2
NetC12_1: C12.1 R22.2 U4.3(IN+)
NetJ3_1: J3.1 R20.1 U4.1(OUT) U4.4(IN-)

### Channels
U_current-sensing-lem/Phase A: designators end in _Phase_A; ports +3.3V_C-V=+3.3V_C-V GND=GND ILEM=ILEM_A ILEM_sense=IFB_U OUTN_i=IFB_U_N OUTN_i_MCU=U_N OUTP_i=IFB_U_P OUTP_i_MCU=U_P
U_current-sensing-lem/Phase C: designators end in _Phase_C; ports +3.3V_C-V=+3.3V_C-V GND=GND ILEM=ILEM_B ILEM_sense=IFB_V OUTN_i=IFB_V_N OUTN_i_MCU=V_N OUTP_i=IFB_V_P OUTP_i_MCU=V_P
U_current-sensing-lem/Phase B: designators end in _Phase_B; ports +3.3V_C-V=+3.3V_C-V GND=GND ILEM=ILEM_B ILEM_sense=IFB_W OUTN_i=IFB_W_N OUTN_i_MCU=VOUT_C_N OUTP_i=IFB_W_P OUTP_i_MCU=VOUT_C_P

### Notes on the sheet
- LEM LF510 current output with G_th=0.2mA/A
- Inverter output operating current I_out=360A RMS (509A peak)
- LEM sensor current output I_lem_x=I_out*G_th=0.2e-3*509=+/- 0.1018A
- ADC input voltage range Vadc = 3.3V
- Voltage drop across the sensing resistor V_sns=I_lem_x*R713=0.1018*27=+/-2.75V
- ADC headroom from rails during normal operation ADC_hr = 10%
- With the given combination of resistors +/- 509A corresponds to cca 0.33 to 2.97V output swing
- -3dB point fc=61.9kHz (simulated)
- TMCS2100 diiferential connection directly to MCU board

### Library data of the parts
C1 = CMP-0006724-5: CAP, CERM, 1000 pF, 100 V, +/- 10%, X7R, 0603; Manufacturer: AVX; TaMin_C: -55°C; ESR_ohm: 2.76d; Polarized: N; SizeAreaWB_mm2: 4.68; Value1: 0.276 ohm; U/M: EA; Value: 1000pF; TaMax_C: 125°C; SizeZ_mm: 1; SizeX_mm: 1.6; SizeY_mm: 0.8; SizeArea_mm2: 1.28; AEC Category: Q200
C8 C14 = CMP-0046668-1: as C3d1 on sheet Voltage-sense-LVside
C10 = CMP-0007078-4: as C9 on sheet Voltage-sense-LVside
C11 = CMP-0079247-1: CAP, CERM, 4700 pF, 100 V,+/- 10%, X7R, AEC-Q200 Grade 1, 0603; Manufacturer: MuRata; TaMin_C: -55°C; Polarized: N; SizeAreaWB_mm2: 4.68; U/M: EA; Value: 4700pF; TaMax_C: 125°C; SizeZ_mm: 1; SizeX_mm: 1.6; SizeY_mm: 0.8; SizeArea_mm2: 1.28; AEC Qualified: Y; Cap_F: 4.7nF; AEC Category: Q200
C12 = CMP-0007075-4: CAP, CERM, 100 pF, 50 V, +/- 5%, C0G/NP0, AEC-Q200 Grade 0, 0603; Manufacturer: TDK; AEC Grade: 0; SizeArea_mm2: 1.28; SizeZ_mm: 1; Value1: Unknown; SizeX_mm: 1.6; Polarized: N; TaMax_C: 150°C; Value2: 50V; Value: 100pF; U/M: EA; AEC Qualified: Y; SizeAreaWB_mm2: 4.68; TaMin_C: -55°C; SizeY_mm: 0.8; AEC Category: Q200
C13 = CMP-0007075-4: as C16 on sheet Voltage-sense-LVside
J3 = CMP-0055256-1: as J1 on sheet Voltage-sense-LVside
R1 R3 = CMP-0025697-4: as R804 on sheet voltage-sensing
R19 R21 = CMP-0078581-1: RES, 1.00 k, 0.1%, 0.1 W, AEC-Q200 Grade 0, 0603; Manufacturer: Panasonic; Power_W: 100mW; TempCo: 25 ppm/C; Value_Code: 1k00; Value: 1.00k; EIA_Code: E192; Res_ohm: 1k; SizeX_mm: 1.6; SizeY_mm: 0.8; SizeZ_mm: 1; Value2: 0.1W; SizeArea_mm2: 1.28; AEC Qualified: Y; AEC Grade: 0; AEC Category: Q200
R20 = CMP-0022003-4: as R9 on sheet Voltage-sense-LVside
R22 = CMP-0022599-4: RES, 7.15 k, 1%, 0.1 W, AEC-Q200 Grade 0, 0603; Manufacturer: Vishay-Dale; Value: 7.15k; Value_Code: 7k15; Power_W: 100mW; Value2: 0.1W; VDC_V: 75V; TempCo: 100 ppm/C; SizeArea_mm2: 1.28; SizeX_mm: 1.6; SizeY_mm: 0.8; SizeZ_mm: 1; EIA_Code: E96; AEC Category: Q200; AEC Qualified: Y; AEC Grade: 0
R23 = CMP-0015563-3: RES, 27.0, 1%, 1 W, AEC-Q200 Grade 0, 2512; Manufacturer: Vishay-Dale; Power_W: 1W; TempCo: 100 ppm/C; Value_Code: 27R0; Value: 27.0; Res_ohm: 27; SizeX_mm: 6.3; SizeY_mm: 3.2; SizeZ_mm: 0.71; SizeArea_mm2: 20.16; AEC Qualified: Y; VDC_V: 500V; AEC Grade: 0; AEC Category: Q200
R24 = CMP-0860901-1: RES, 24.9 k, 0.1%, 0.1 W, AEC-Q200 Grade 0, 0603; Manufacturer: Panasonic; AEC Qualified: Y; Value_Code: 24k9; SizeArea_mm2: 1.28; SizeAreaWB_mm2: 4.68; Value2: 0.1W; Power_W: 100mW; SizeZ_mm: 1; VDC_V: 75V; Value: 24.9k; AEC Grade: 0; TempCo: 25 ppm/C; SizeY_mm: 0.8; AEC Category: Q200; EIA_Code: E192; SizeX_mm: 1.6
U4 = CMP-0120546-1: as U3 on sheet Voltage-sense-LVside

## Sheet resolver.SchDoc: Resolver Analog Front-End
size 431 x 279 mm; Date: Not shown in title block; ApprovedBy: Not shown in title block; CheckedBy: Not shown in title block; Author: Not shown in title block; CompanyName: Not shown in title block; DrawnBy: Panacek; Engineer: Not shown in title block; Organization: Not shown in title block; Address1: Not shown in title block; Address2: Not shown in title block; Address3: Not shown in title block; Address4: Not shown in title block; DocumentNumber: 5; Revision: Use project parameter SCH_Rev; SheetNumber: 5; SheetTotal: 19; PageSetup: Record=PageOptions¦CenterHorizontal=True¦CenterVertical=True¦PrintScale=1.00¦XCorrection=1.00¦YCorrection=1.00¦PrintKind=0¦BorderSize=5000000¦LeftOffset=0¦BottomOffset=0¦Orientation=2¦PaperLength=1000¦PaperWidth=1000¦Scale=100¦PaperSource=15¦PrintQuality=600¦MediaType=1¦DitherType=10¦PaperKind=Letter¦PrintScaleMode=1
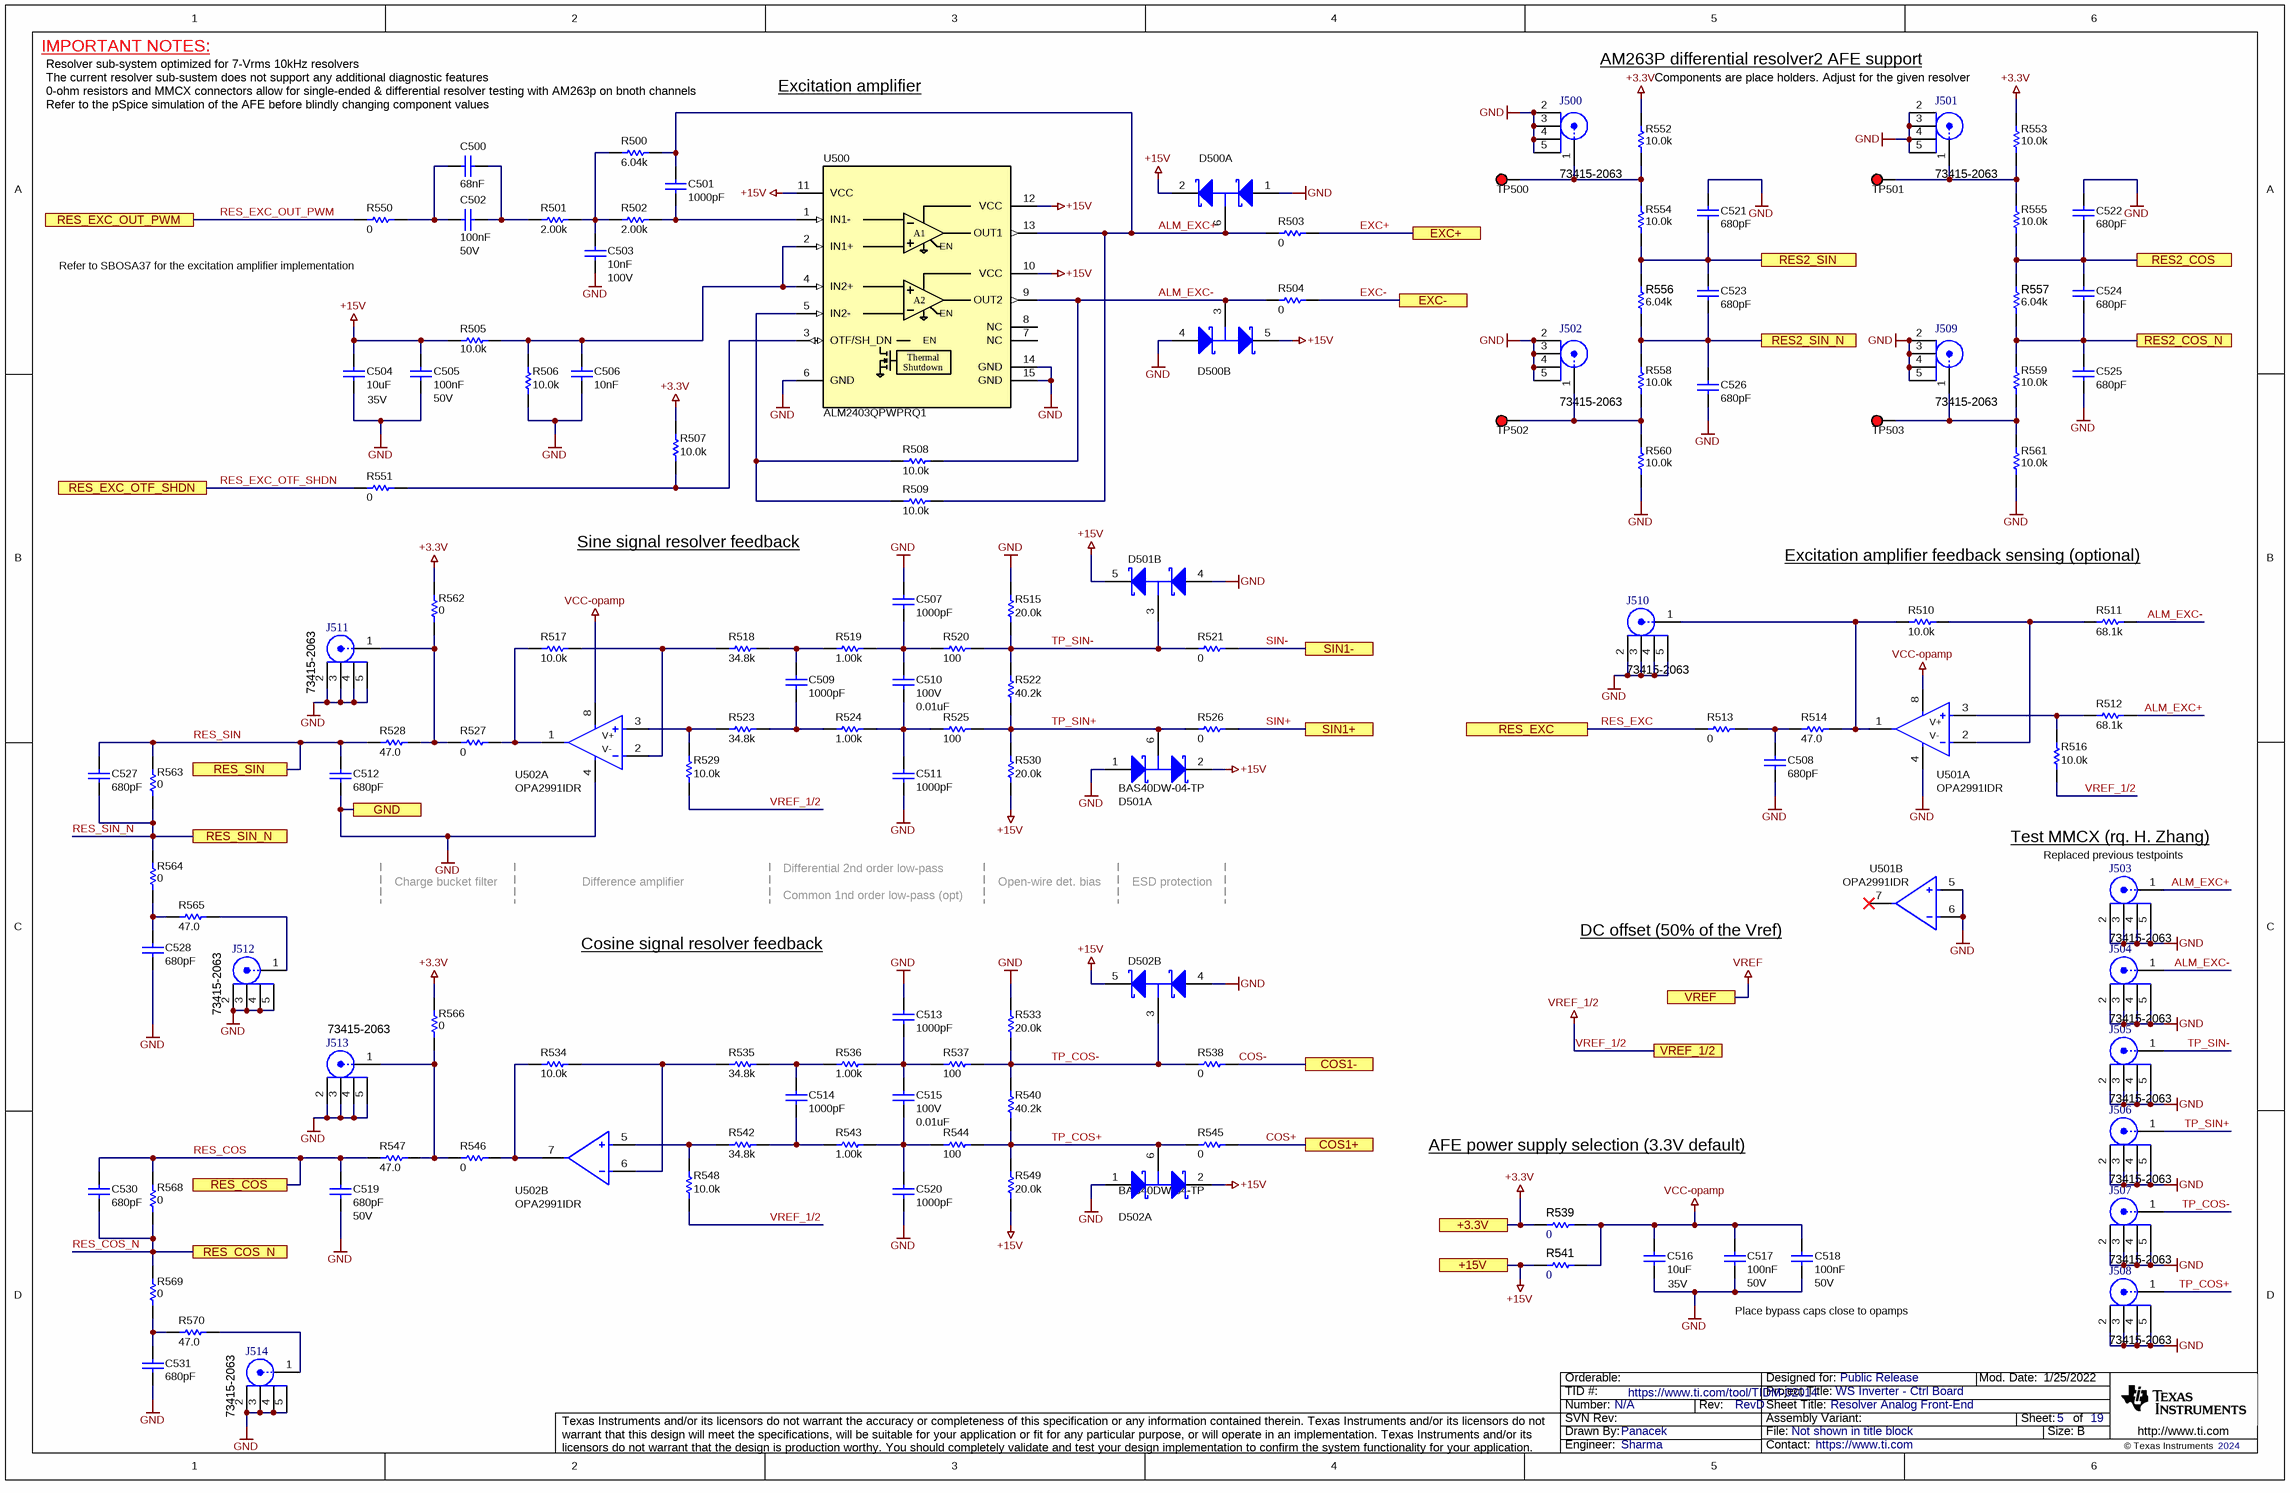
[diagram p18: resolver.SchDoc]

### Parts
C500  Cap_F: 68nF  [0603]  (hidden comment: CGA3E2X7R1H683K080AA)
C501  ValueDisplayed: 1000pF  [0603]  (hidden comment: GRM1885C1H102JA01D)
C502  Cap_F: 100nF  VDC_V: 50V  [0603]  (hidden comment: CGA3E2X7R1H104K080AA)
C503  Cap_F: 10nF  VDC_V: 100V  [0603]  (hidden comment: CGA3E2X7R2A103K080AA)
C504  ValueDisplayed: 10uF  Value2: 35V  [0603]  (hidden comment: GRM188R6YA106MA73D)
C505  Cap_F: 100nF  VDC_V: 50V  [0603]  (hidden comment: CGA3E2X7R1H104K080AA)
C506  Cap_F: 10nF  [0603]  (hidden comment: CGA3E2X7R2A103K080AA)
C507  ValueDisplayed: 1000pF  [0603]  (hidden comment: GRM1885C1H102JA01D)
C508  ValueDisplayed: 680pF  [0603]  (hidden comment: C0603C681J5GACTU)
C509  ValueDisplayed: 1000pF  [0603]  (hidden comment: GRM1885C1H102JA01D)
C510  VDC_V: 100V  ValueDisplayed: 0.01uF  [0603]  (hidden comment: CGA3E2X7R2A103K080AA)
C511  ValueDisplayed: 1000pF  [0603]  (hidden comment: GRM1885C1H102JA01D)
C512  ValueDisplayed: 680pF  [0603]  (hidden comment: C0603C681J5GACTU)
C513  ValueDisplayed: 1000pF  [0603]  (hidden comment: GRM1885C1H102JA01D)
C514  ValueDisplayed: 1000pF  [0603]  (hidden comment: GRM1885C1H102JA01D)
C515  VDC_V: 100V  ValueDisplayed: 0.01uF  [0603]  (hidden comment: CGA3E2X7R2A103K080AA)
C516  ValueDisplayed: 10uF  Value2: 35V  [0603]  (hidden comment: GRM188R6YA106MA73D)
C517  Cap_F: 100nF  VDC_V: 50V  [0603]  (hidden comment: CGA3E2X7R1H104K080AA)
C518  Cap_F: 100nF  VDC_V: 50V  [0603]  (hidden comment: CGA3E2X7R1H104K080AA)
C519  ValueDisplayed: 680pF  VDC_V: 50V  [0603]  (hidden comment: C0603C681J5GACTU)
C520  ValueDisplayed: 1000pF  [0603]  (hidden comment: GRM1885C1H102JA01D)
C521  ValueDisplayed: 680pF  [0603]  (hidden comment: C0603C681J5GACTU)
C522  ValueDisplayed: 680pF  [0603]  (hidden comment: C0603C681J5GACTU)
C523  ValueDisplayed: 680pF  [0603]  (hidden comment: C0603C681J5GACTU)
C524  ValueDisplayed: 680pF  [0603]  (hidden comment: C0603C681J5GACTU)
C525  ValueDisplayed: 680pF  [0603]  (hidden comment: C0603C681J5GACTU)
C526  ValueDisplayed: 680pF  [0603]  (hidden comment: C0603C681J5GACTU)
C527  ValueDisplayed: 680pF  [0603]  (hidden comment: C0603C681J5GACTU)
C528  ValueDisplayed: 680pF  [0603]  (hidden comment: C0603C681J5GACTU)
C530  ValueDisplayed: 680pF  [0603]  (hidden comment: C0603C681J5GACTU)
C531  ValueDisplayed: 680pF  [0603]  (hidden comment: C0603C681J5GACTU)
D500  BAS40DW-04-TP  [SOT-363]  (value not drawn)  (parts A,B of 2)
D501  BAS40DW-04-TP  [SOT-363]  (value not drawn)  (parts A,B of 2)
D502  BAS40DW-04-TP  [SOT-363]  (value not drawn)  (parts A,B of 2)
J500  73415-2063  [Molex_73415-2063]
J501  73415-2063  [Molex_73415-2063]
J502  73415-2063  [Molex_73415-2063]
J503  73415-2063  [Molex_73415-2063]
J504  73415-2063  [Molex_73415-2063]
J505  73415-2063  [Molex_73415-2063]
J506  73415-2063  [Molex_73415-2063]
J507  73415-2063  [Molex_73415-2063]
J508  73415-2063  [Molex_73415-2063]
J509  73415-2063  [Molex_73415-2063]
J510  73415-2063  [Molex_73415-2063]
J511  73415-2063  [Molex_73415-2063]
J512  73415-2063  [Molex_73415-2063]
J513  73415-2063  [Molex_73415-2063]
J514  73415-2063  [Molex_73415-2063]
R500  ValueDisplayed: 6.04k  [0603]  (hidden comment: CRCW06036K04FKEA)
R501  ValueDisplayed: 2.00k  [0603]  (hidden comment: CRCW06032K00FKEA)
R502  ValueDisplayed: 2.00k  [0603]  (hidden comment: CRCW06032K00FKEA)
R503  ValueDisplayed: 0  [0603]  (hidden comment: CRCW06030000Z0EA)
R504  ValueDisplayed: 0  [0603]  (hidden comment: CRCW06030000Z0EA)
R505  ValueDisplayed: 10.0k  [0603]  (hidden comment: CRCW060310K0FKEA)
R506  ValueDisplayed: 10.0k  [0603]  (hidden comment: CRCW060310K0FKEA)
R507  ValueDisplayed: 10.0k  [0603]  (hidden comment: CRCW060310K0FKEA)
R508  ValueDisplayed: 10.0k  [0603]  (hidden comment: CRCW060310K0FKEA)
R509  ValueDisplayed: 10.0k  [0603]  (hidden comment: CRCW060310K0FKEA)
R510  ValueDisplayed: 10.0k  [0603]  (hidden comment: CRCW060310K0FKEA)
R511  ValueDisplayed: 68.1k  [0603]  (hidden comment: CRCW060368K1FKEA)
R512  ValueDisplayed: 68.1k  [0603]  (hidden comment: CRCW060368K1FKEA)
R513  ValueDisplayed: 0  [0603]  (hidden comment: CRCW06030000Z0EA)
R514  ValueDisplayed: 47.0  [0603]  (hidden comment: CRCW060347R0FKEA)
R515  ValueDisplayed: 20.0k  [0603]  (hidden comment: CRCW060320K0FKEA)
R516  ValueDisplayed: 10.0k  [0603]  (hidden comment: CRCW060310K0FKEA)
R517  ValueDisplayed: 10.0k  [0603]  (hidden comment: CRCW060310K0FKEA)
R518  ValueDisplayed: 34.8k  [0603]  (hidden comment: CRCW060334K8FKEA)
R519  ValueDisplayed: 1.00k  [0603]  (hidden comment: CRCW06031K00FKEA)
R520  ValueDisplayed: 100  [0603]  (hidden comment: CRCW0603100RFKEA)
R521  ValueDisplayed: 0  [0603]  (hidden comment: CRCW06030000Z0EA)
R522  ValueDisplayed: 40.2k  [0603]  (hidden comment: CRCW060340K2FKEA)
R523  ValueDisplayed: 34.8k  [0603]  (hidden comment: CRCW060334K8FKEA)
R524  ValueDisplayed: 1.00k  [0603]  (hidden comment: CRCW06031K00FKEA)
R525  ValueDisplayed: 100  [0603]  (hidden comment: CRCW0603100RFKEA)
R526  ValueDisplayed: 0  [0603]  (hidden comment: CRCW06030000Z0EA)
R527  ValueDisplayed: 0  [0603]  (hidden comment: CRCW06030000Z0EA)
R528  ValueDisplayed: 47.0  [0603]  (hidden comment: CRCW060347R0FKEA)
R529  ValueDisplayed: 10.0k  [0603]  (hidden comment: CRCW060310K0FKEA)
R530  ValueDisplayed: 20.0k  [0603]  (hidden comment: CRCW060320K0FKEA)
R533  ValueDisplayed: 20.0k  [0603]  (hidden comment: CRCW060320K0FKEA)
R534  ValueDisplayed: 10.0k  [0603]  (hidden comment: CRCW060310K0FKEA)
R535  ValueDisplayed: 34.8k  [0603]  (hidden comment: CRCW060334K8FKEA)
R536  ValueDisplayed: 1.00k  [0603]  (hidden comment: CRCW06031K00FKEA)
R537  ValueDisplayed: 100  [0603]  (hidden comment: CRCW0603100RFKEA)
R538  ValueDisplayed: 0  [0603]  (hidden comment: CRCW06030000Z0EA)
R539  ValueDisplayed: 0  [5106]  (hidden comment: 5106)
R540  ValueDisplayed: 40.2k  [0603]  (hidden comment: CRCW060340K2FKEA)
R541  ValueDisplayed: 0  [5106]  (hidden comment: 5106)
R542  ValueDisplayed: 34.8k  [0603]  (hidden comment: CRCW060334K8FKEA)
R543  ValueDisplayed: 1.00k  [0603]  (hidden comment: CRCW06031K00FKEA)
R544  ValueDisplayed: 100  [0603]  (hidden comment: CRCW0603100RFKEA)
R545  ValueDisplayed: 0  [0603]  (hidden comment: CRCW06030000Z0EA)
R546  ValueDisplayed: 0  [0603]  (hidden comment: CRCW06030000Z0EA)
R547  ValueDisplayed: 47.0  [0603]  (hidden comment: CRCW060347R0FKEA)
R548  ValueDisplayed: 10.0k  [0603]  (hidden comment: CRCW060310K0FKEA)
R549  ValueDisplayed: 20.0k  [0603]  (hidden comment: CRCW060320K0FKEA)
R550  ValueDisplayed: 0  [0603]  (hidden comment: CRCW06030000Z0EA)
R551  ValueDisplayed: 0  [0603]  (hidden comment: CRCW06030000Z0EA)
R552  ValueDisplayed: 10.0k  [0603]  (hidden comment: CRCW060310K0FKEA)
R553  ValueDisplayed: 10.0k  [0603]  (hidden comment: CRCW060310K0FKEA)
R554  ValueDisplayed: 10.0k  [0603]  (hidden comment: CRCW060310K0FKEA)
R555  ValueDisplayed: 10.0k  [0603]  (hidden comment: CRCW060310K0FKEA)
R556  ValueDisplayed: 6.04k  [0603]  (hidden comment: CRCW06036K04FKEA)
R557  ValueDisplayed: 6.04k  [0603]  (hidden comment: CRCW06036K04FKEA)
R558  ValueDisplayed: 10.0k  [0603]  (hidden comment: CRCW060310K0FKEA)
R559  ValueDisplayed: 10.0k  [0603]  (hidden comment: CRCW060310K0FKEA)
R560  ValueDisplayed: 10.0k  [0603]  (hidden comment: CRCW060310K0FKEA)
R561  ValueDisplayed: 10.0k  [0603]  (hidden comment: CRCW060310K0FKEA)
R562  ValueDisplayed: 0  [0603]  (hidden comment: CRCW06030000Z0EA)
R563  ValueDisplayed: 0  [0603]  (hidden comment: CRCW06030000Z0EA)
R564  ValueDisplayed: 0  [0603]  (hidden comment: CRCW06030000Z0EA)
R565  ValueDisplayed: 47.0  [0603]  (hidden comment: CRCW060347R0FKEA)
R566  ValueDisplayed: 0  [0603]  (hidden comment: CRCW06030000Z0EA)
R568  ValueDisplayed: 0  [0603]  (hidden comment: CRCW06030000Z0EA)
R569  ValueDisplayed: 0  [0603]  (hidden comment: CRCW06030000Z0EA)
R570  ValueDisplayed: 47.0  [0603]  (hidden comment: CRCW060347R0FKEA)
TP500  5000  [Keystone5000]  (value not drawn)
TP501  5000  [Keystone5000]  (value not drawn)
TP502  5000  [Keystone5000]  (value not drawn)
TP503  5000  [Keystone5000]  (value not drawn)
U500  ALM2403QPWPRQ1  [PWP0014H_N]
U501  OPA2991IDR  [D0008A-MFG]  (parts A,B of 2)
U502  OPA2991IDR  [D0008A-MFG]  (parts A,B of 2)

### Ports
+3.3V, +15V, COS1+, COS1-, EXC+, EXC-, GND, RES2_COS, RES2_COS_N, RES2_SIN, RES2_SIN_N, RES_COS, RES_COS_N, RES_EXC, RES_EXC_OTF_SHDN, RES_EXC_OUT_PWM, RES_SIN, RES_SIN_N, SIN1+, SIN1-, VREF, VREF_1/2

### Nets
+3.3V: R507.2 R539.1 R552.1 R553.1 R562.2 R566.2 ; port +3.3V
+15V: C504.1 C505.1 D500.2(C1) D500.5(C2) D501.2(C1) D501.5(C2) D502.2(C1) D502.5(C2) R505.2 R530.1 R541.1 R549.1 U500.10(VCC) U500.11(VCC) U500.12(VCC) ; port +15V
GND: C503.2 C504.2 C505.2 C506.1 C507.2 C508.1 C511.1 C512.1 C513.2 C516.2 C517.2 C518.2 C519.1 C520.1 C521.2 C522.2 C525.1 C526.1 C528.1 C531.1 D500.1(A1) D500.4(A2) D501.1(A1) D501.4(A2) D502.1(A1) D502.4(A2) J500.2 J500.3 J500.4 J500.5 J501.2 J501.3 J501.4 J501.5 J502.2 J502.3 J502.4 J502.5 J503.2 J503.3 J503.4 J503.5 J504.2 J504.3 J504.4 J504.5 J505.2 J505.3 J505.4 J505.5 J506.2 J506.3 J506.4 J506.5 J507.2 J507.3 J507.4 J507.5 J508.2 J508.3 J508.4 J508.5 J509.2 J509.3 J509.4 J509.5 J510.2 J510.3 J510.4 J510.5 J511.2 J511.3 J511.4 J511.5 J512.2 J512.3 J512.4 J512.5 J513.2 J513.3 J513.4 J513.5 J514.2 J514.3 J514.4 J514.5 R506.1 R515.2 R533.2 R560.1 R561.1 U500.6(GND) U500.14(GND) U500.15(GND) U501.4(V-) U501.5(IN2+) U501.6(IN2-) U502.4(V-) ; port GND
VCC-opamp: C516.1 C517.1 C518.1 R539.2 R541.2 U501.8(V+) U502.8(V+)
VREF_1/2: R516.1 R529.1 R548.1 ; port VREF_1/2
ALM_EXC+: C501.2 D500.6(AC1) J503.1 R500.2 R503.1 R509.1 R512.2 U500.13(OUT1)  [project net ALM_EXC+_5]
ALM_EXC-: D500.3(AC2) J504.1 R504.1 R508.1 R511.2 U500.9(OUT2)  [project net ALM_EXC-_5]
COS+: R545.2 ; port COS1+
COS-: R538.2 ; port COS1-
EXC+: R503.2 ; port EXC+
EXC-: R504.2 ; port EXC-
RES2_COS: C522.1 C524.2 R555.1 R557.2 ; port RES2_COS
RES2_COS_N: C524.1 C525.2 R557.1 R559.2 ; port RES2_COS_N
RES2_SIN: C521.1 C523.2 R554.1 R556.2 ; port RES2_SIN
RES2_SIN_N: C523.1 C526.2 R556.1 R558.2 ; port RES2_SIN_N
RES_COS: C519.2 C530.2 R547.2 R568.2 ; port RES_COS
RES_COS_N: C530.1 R568.1 R569.2 ; port RES_COS_N
RES_EXC: R513.1 ; port RES_EXC
RES_EXC_OTF_SHDN: R551.1 ; port RES_EXC_OTF_SHDN  [project net EXC_OC_OT]
RES_EXC_OUT_PWM: R550.1 ; port RES_EXC_OUT_PWM
RES_SIN: C512.2 C527.2 R528.2 R563.2 ; port RES_SIN
RES_SIN_N: C527.1 R563.1 R564.2 ; port RES_SIN_N
SIN+: R526.2 ; port SIN1+
SIN-: R521.2 ; port SIN1-
TP_COS+: D502.6(AC1) J508.1 R540.1 R544.2 R545.1 R549.2  [project net TP_COS+_5]
TP_COS-: D502.3(AC2) J507.1 R533.1 R537.2 R538.1 R540.2  [project net TP_COS-_5]
TP_SIN+: D501.6(AC1) J506.1 R522.1 R525.2 R526.1 R530.2  [project net TP_SIN+_5]
TP_SIN-: D501.3(AC2) J505.1 R515.1 R520.2 R521.1 R522.2  [project net TP_SIN-_5]
NetC500_1: C500.1 C502.2 R550.2
NetC500_2: C500.2 C502.1 R501.1
NetC501_1: C501.1 R502.2 U500.1(IN1-)
NetC503_1: C503.1 R500.1 R501.2 R502.1
NetC506_2: C506.2 R505.1 R506.2 U500.2(IN1+) U500.4(IN2+)
NetC507_1: C507.1 C510.1 R519.2 R520.1
NetC508_2: C508.2 R513.2 R514.2
NetC509_1: C509.1 R523.2 R524.1
NetC509_2: C509.2 R518.2 R519.1
NetC510_2: C510.2 C511.2 R524.2 R525.1
NetC513_1: C513.1 C515.1 R536.2 R537.1
NetC514_1: C514.1 R542.2 R543.1
NetC514_2: C514.2 R535.2 R536.1
NetC515_2: C515.2 C520.2 R543.2 R544.1
NetC528_2: C528.2 R564.1 R565.2
NetC531_2: C531.2 R569.1 R570.2
NetJ500_1: J500.1 R552.2 R554.2 TP500.1
NetJ501_1: J501.1 R553.2 R555.2 TP501.1
NetJ502_1: J502.1 R558.1 R560.2 TP502.1
NetJ509_1: J509.1 R559.1 R561.2 TP503.1
NetJ510_1: J510.1 R510.2 R514.1 U501.1(OUT1)
NetJ511_1: J511.1 R527.1 R528.1 R562.1
NetJ512_1: J512.1 R565.1
NetJ513_1: J513.1 R546.1 R547.1 R566.1
NetJ514_1: J514.1 R570.1
NetR507_1: R507.1 R551.2 U500.3(OTF/SH_DN)
NetR508_2: R508.2 R509.2 U500.5(IN2-)
NetR510_1: R510.1 R511.1 U501.2(IN1-)
NetR512_1: R512.1 R516.2 U501.3(IN1+)
NetR517_1: R517.1 R518.1 U502.2(IN1-)
NetR517_2: R517.2 R527.2 U502.1(OUT1)
NetR523_1: R523.1 R529.2 U502.3(IN1+)
NetR534_1: R534.1 R535.1 U502.6(IN2-)
NetR534_2: R534.2 R546.2 U502.7(OUT2)
NetR542_1: R542.1 R548.2 U502.5(IN2+)

Not connected (* = marked no-connect by the designer): U500 7(NC) 8(NC); U501 7(OUT2)*

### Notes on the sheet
- Resolver sub-system optimized for 7-Vrms 10kHz resolvers
- The current resolver sub-sustem does not support any additional diagnostic features
- 0-ohm resistors and MMCX connectors allow for single-ended & differential resolver testing with AM263p on bnoth channels
- IMPORTANT NOTES:
- Excitation amplifier
- Components are place holders. Adjust for the given resolver
- AM263P differential resolver2 AFE support
- Refer to the pSpice simulation of the AFE before blindly changing component values
- (near R550) Refer to SBOSA37 for the excitation amplifier implementation
- Sine signal resolver feedback
- Excitation amplifier feedback sensing (optional)
- Test MMCX (rq. H. Zhang)
- Charge bucket filter
- Difference amplifier
- Differential 2nd order low-pass
- Common 1nd order low-pass (opt)
- Open-wire det. bias
- ESD protection
- (near J503) Replaced previous testpoints
- Cosine signal resolver feedback
- DC offset (50% of the Vref)
- AFE power supply selection (3.3V default)
- Place bypass caps close to opamps

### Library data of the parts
C500 = CMP-0007080-5: CAP, CERM, 0.068 uF, 50 V, +/- 10%, X7R, AEC-Q200 Grade 1, 0603; Manufacturer: TDK; TaMin_C: -55°C; Polarized: N; SizeAreaWB_mm2: 4.68; Value1: 0.035979 ohm; U/M: EA; TaMax_C: 125°C; SizeZ_mm: 1; SizeX_mm: 1.6; Value2: 50V; SizeArea_mm2: 1.28; AEC Qualified: Y; AEC Category: Q200; SizeY_mm: 0.8; ESR_ohm: 35.979m; IRMS_A: 886.483mA
C501 C507 C509 C511 C513 C514 C520 = CMP-0007173-4: CAP, CERM, 1000 pF, 50 V, +/- 5%, C0G/NP0, 0603; Manufacturer: MuRata; Polarized: N; Value: 1000pF; U/M: EA; Cap_F: 1nF; Value1: Unknown; VDC_V: 50V; TaMin_C: -55°C; TaMax_C: 125°C; AEC Category: Q200; SizeArea_mm2: 1.28; SizeAreaWB_mm2: 4.68; SizeX_mm: 1.6; SizeY_mm: 0.8; SizeZ_mm: 1
C502 C505 C517 C518 = CMP-0007078-4: as C9 on sheet Voltage-sense-LVside
C503 = CMP-0007082-4: CAP, CERM, 0.01 uF, 100 V, +/- 10%, X7R, AEC-Q200 Grade 1, 0603; Manufacturer: TDK; TaMin_C: -55°C; Polarized: N; SizeAreaWB_mm2: 4.68; Value1: 0.235428 ohm; U/M: EA; Value: 0.01uF; TaMax_C: 125°C; SizeZ_mm: 1; SizeX_mm: 1.6; SizeY_mm: 0.8; SizeArea_mm2: 1.28; AEC Qualified: Y; AEC Category: Q200; ESR_ohm: 0.2354; IRMS_A: 396.995mA
C504 C516 = CMP-0007355-6: CAP, CERM, 10 uF, 35 V, +/- 20%, X5R, 0603; Manufacturer: Murata; Polarized: N; Value: 10uF; U/M: EA; Cap_F: 10µF; Value1: Unknown; TaMin_C: -55°C; TaMax_C: 85°C; SizeArea_mm2: 1.28; SizeAreaWB_mm2: 4.68; SizeX_mm: 1.6; SizeY_mm: 0.8; SizeZ_mm: 1; AEC Category: Q200
C506 = CMP-0007082-4: CAP, CERM, 0.01 uF, 100 V, +/- 10%, X7R, AEC-Q200 Grade 1, 0603; Manufacturer: TDK; Polarized: N; Value: 0.01uF; U/M: EA; ESR_ohm: 0.2354; Value1: 0.235428 ohm; VDC_V: 100V; IRMS_A: 396.995mA; TaMin_C: -55°C; TaMax_C: 125°C; AEC Category: Q200; AEC Qualified: Y; AEC Grade: 1; SizeArea_mm2: 1.28; SizeAreaWB_mm2: 4.68; SizeX_mm: 1.6; SizeY_mm: 0.8
C508 C512 C521-C528 C530 C531 = CMP-0006959-4: CAP, CERM, 680 pF, 50 V, +/- 5%, C0G/NP0, 0603; Manufacturer: Kemet; Polarized: N; Value: 680pF; U/M: EA; Value1: Unknown; VDC_V: 50V; TaMin_C: -55°C; TaMax_C: 125°C; AEC Category: Q200; SizeArea_mm2: 1.28; SizeAreaWB_mm2: 4.68; SizeX_mm: 1.6; SizeY_mm: 0.8; SizeZ_mm: 1
C510 C515 = CMP-0007082-4: CAP, CERM, 0.01 uF, 100 V, +/- 10%, X7R, AEC-Q200 Grade 1, 0603; Manufacturer: TDK; TaMin_C: -55°C; Polarized: N; SizeAreaWB_mm2: 4.68; Value1: 0.235428 ohm; U/M: EA; Value: 0.01uF; TaMax_C: 125°C; SizeZ_mm: 1; SizeX_mm: 1.6; SizeY_mm: 0.8; SizeArea_mm2: 1.28; AEC Qualified: Y; Cap_F: 10nF; AEC Category: Q200; ESR_ohm: 0.2354; IRMS_A: 396.995mA
C519 = CMP-0006959-4: CAP, CERM, 680 pF, 50 V, +/- 5%, C0G/NP0, 0603; Manufacturer: Kemet; Polarized: N; Value: 680pF; U/M: EA; Value1: Unknown; TaMin_C: -55°C; TaMax_C: 125°C; AEC Category: Q200; SizeArea_mm2: 1.28; SizeAreaWB_mm2: 4.68; SizeX_mm: 1.6; SizeY_mm: 0.8; SizeZ_mm: 1
D500-D502 = CMP-0028604-2: Diode, Schottky, 40 V, 0.2 A, SOT-363; Manufacturer: Micro Commercial Components; Vf_V: 1V; Value: 40V; Value1: 0.2A; Io_A: 200mA; TJmax_C: 125°C; SizeAreaWB_mm2: 10.24; SizeArea_mm2: 4.84; SizeX_mm: 2.2; SizeZ_mm: 1.1; AEC Category: Q101; Green_Lifecycle: Not Set; Green_REACh: Incomplete
J500-J514 = CMP-0055256-1: as J1 on sheet Voltage-sense-LVside
R500 = CMP-0022558-4: RES, 6.04 k, 1%, 0.1 W, AEC-Q200 Grade 0, 0603; Manufacturer: Vishay-Dale; Value: 6.04k; Value_Code: 6k04; Power_W: 100mW; Value2: 0.1W; VDC_V: 75V; TempCo: 100 ppm/C; SizeArea_mm2: 1.28; SizeX_mm: 1.6; SizeY_mm: 0.8; SizeZ_mm: 1; EIA_Code: E96; AEC Category: Q200; AEC Qualified: Y; AEC Grade: 0
R501 R502 = CMP-0022268-4: RES, 2.00 k, 1%, 0.1 W, AEC-Q200 Grade 0, 0603; Manufacturer: Vishay-Dale; Value: 2.00k; Res_ohm: 2k; Value_Code: 2k00; Power_W: 100mW; Value2: 0.1W; VDC_V: 75V; TempCo: 100 ppm/C; SizeArea_mm2: 1.28; SizeX_mm: 1.6; SizeY_mm: 0.8; SizeZ_mm: 1; EIA_Code: E96; AEC Category: Q200; AEC Qualified: Y; AEC Grade: 0
R503 R504 R513 R521 R526 R527 R538 R545 R546 R550 R551 R562-R564 R566 R568 R569 = CMP-0025697-4: RES, 0, 5%, 0.1 W, AEC-Q200 Grade 0, 0603; Manufacturer: Vishay-Dale; Value_Code: 0000; SizeArea_mm2: 1.28; AEC Qualified: Y; AEC Category: Q200; Value: 0; SizeZ_mm: 1; SizeY_mm: 0.8; Power_W: 100mW; Value2: 0.1W; SizeX_mm: 1.6; EIA_Code: E24; TempCo: 200 ppm/C; VDC_V: 75V
R505-R510 R516 R517 R529 R534 R548 = CMP-0021998-4: RES, 10.0 k, 1%, 0.1 W, AEC-Q200 Grade 0, 0603; Manufacturer: Vishay-Dale; Value: 10.0k; Res_ohm: 10k; Value_Code: 10k0; Power_W: 100mW; Value2: 0.1W; VDC_V: 75V; TempCo: 100 ppm/C; EIA_Code: E96; AEC Category: Q200; AEC Qualified: Y; AEC Grade: 0; SizeArea_mm2: 1.28; SizeX_mm: 1.6; SizeY_mm: 0.8; SizeZ_mm: 1
R511 R512 = CMP-0022552-4: RES, 68.1 k, 1%, 0.1 W, AEC-Q200 Grade 0, 0603; Manufacturer: Vishay-Dale; Power_W: 100mW; TempCo: 100 ppm/C; Value_Code: 68k1; Value: 68.1k; EIA_Code: E96; SizeX_mm: 1.6; SizeY_mm: 0.8; SizeZ_mm: 1; Value2: 0.1W; SizeArea_mm2: 1.28; AEC Qualified: Y; VDC_V: 75V; AEC Category: Q200; AEC Grade: 0
R514 R528 R547 R565 R570 = CMP-0081280-1: RES, 47.0, 1%, 0.1 W, AEC-Q200 Grade 0, 0603; Manufacturer: Vishay-Dale; Value: 47.0; Res_ohm: 47; Value_Code: 47R0; Power_W: 100mW; Value2: 0.1W; VDC_V: 75V; TempCo: 100 ppm/C; AEC Category: Q200; AEC Qualified: Y; AEC Grade: 0; SizeArea_mm2: 1.28; SizeX_mm: 1.6; SizeY_mm: 0.8; SizeZ_mm: 1; SizeAreaWB_mm2: 4.68
R515 R530 R533 R549 = CMP-0022204-4: RES, 20.0 k, 1%, 0.1 W, AEC-Q200 Grade 0, 0603; Manufacturer: Vishay-Dale; Value: 20.0k; Res_ohm: 20k; Value_Code: 20k0; Power_W: 100mW; Value2: 0.1W; VDC_V: 75V; TempCo: 100 ppm/C; EIA_Code: E96; AEC Category: Q200; AEC Qualified: Y; AEC Grade: 0; SizeArea_mm2: 1.28; SizeX_mm: 1.6; SizeY_mm: 0.8; SizeZ_mm: 1
R518 R523 R535 R542 = CMP-0022347-4: RES, 34.8 k, 1%, 0.1 W, AEC-Q200 Grade 0, 0603; Manufacturer: Vishay-Dale; Power_W: 100mW; TempCo: 100 ppm/C; Value_Code: 34k8; Value: 34.8k; EIA_Code: E96; SizeX_mm: 1.6; SizeY_mm: 0.8; SizeZ_mm: 1; Value2: 0.1W; SizeArea_mm2: 1.28; AEC Qualified: Y; VDC_V: 75V; AEC Category: Q200; AEC Grade: 0
R519 R524 R536 R543 = CMP-0022109-5: RES, 1.00 k, 1%, 0.1 W, AEC-Q200 Grade 0, 0603; Manufacturer: Vishay-Dale; Power_W: 100mW; TempCo: 100 ppm/C; Value_Code: 1k00; Value: 1.00k; EIA_Code: E96; Res_ohm: 1k; SizeX_mm: 1.6; SizeY_mm: 0.8; SizeZ_mm: 1; Value2: 0.1W; SizeArea_mm2: 1.28; AEC Qualified: Y; VDC_V: 75V; AEC Category: Q200; AEC Grade: 0
R520 R525 R537 R544 = CMP-0021991-4: RES, 100, 1%, 0.1 W, AEC-Q200 Grade 0, 0603; Manufacturer: Vishay-Dale; Power_W: 100mW; TempCo: 100 ppm/C; Value_Code: 100R; Value: 100; EIA_Code: E96; SizeX_mm: 1.6; SizeY_mm: 0.8; SizeZ_mm: 1; Value2: 0.1W; SizeArea_mm2: 1.28; AEC Qualified: Y; VDC_V: 75V; AEC Category: Q200; AEC Grade: 0
R522 R540 = CMP-0022410-4: RES, 40.2 k, 1%, 0.1 W, AEC-Q200 Grade 0, 0603; Manufacturer: Vishay-Dale; Power_W: 100mW; TempCo: 100 ppm/C; Value_Code: 40k2; Value: 40.2k; EIA_Code: E96; SizeX_mm: 1.6; SizeY_mm: 0.8; SizeZ_mm: 1; Value2: 0.1W; SizeArea_mm2: 1.28; AEC Qualified: Y; VDC_V: 75V; AEC Category: Q200; AEC Grade: 0
R539 R541 = CMP-0020833-2: as R10jump on sheet Voltage-sense-LVside
R552-R555 R558-R561 = CMP-0021998-4: as R4 on sheet Safe State Behavior Settings
R556 R557 = CMP-0022558-4: RES, 6.04 k, 1%, 0.1 W, AEC-Q200 Grade 0, 0603; Manufacturer: Vishay-Dale; Power_W: 100mW; TempCo: 100 ppm/C; Value_Code: 6k04; Value: 6.04k; EIA_Code: E96; SizeX_mm: 1.6; SizeY_mm: 0.8; SizeZ_mm: 1; Value2: 0.1W; SizeArea_mm2: 1.28; AEC Qualified: Y; VDC_V: 75V; AEC Category: Q200; AEC Grade: 0
TP500-TP503 = CMP-0055137-2: Test Point, Miniature, Red, TH; Manufacturer: Keystone Electronics; Green_REACh: Passed; Green_Lifecycle: Active; ContactFinish: Silver; CNHeader: FALSE; CT: TRUE
U500 = CMP-0861002-1: 24-V, High-Current, Wide-Bandwidth, Dual Operational Amplifier, PWP0014H (HTSSOP-14); Manufacturer: Texas Instruments; AEC Category: Q200; CompType: IC; SizeAreaWB_mm2: 58.8; SizeY_mm: 5; SizeZ_mm: 1.2; SizeArea_mm2: 32; AEC Qualified: N; SizeX_mm: 6.4
U501 U502 = CMP-0094081-1: 40-V, dual 4.5MHz, rail-to-rail input/output, low-offset-voltage, low-noise op amp 8-SOIC -40 to 125; Manufacturer: Texas Instruments; TaMin_C: -40°C; Number Of Channels: 2; SizeZ_mm: 1.75mm; Standoff Height: 0.11mm; Response Time: 2.5us; Max Dual Supply Voltage: 20V; Max Supply Voltage: 40V; TaMax_C: +125°C; Voltage Gain: 120dB; Output Current Per Channel: 75mA; Input Bias Current: 0.00001uA; Min Dual Supply Voltage: 1.35V; AEC Qualified: No; Nominal Supply Current: 560uA; Input Offset Voltage: 0.125mV; TJmax_C: +150°C; Min Supply Voltage: 2.7V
